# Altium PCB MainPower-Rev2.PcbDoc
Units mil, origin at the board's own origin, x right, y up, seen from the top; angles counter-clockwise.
Board outline 7780 x 7780 mil, 4 copper layers (Top Layer, Internal Plane 1, Internal Plane 2, Bottom Layer); 128 components, 89 nets, 530 pads, 24 vias.
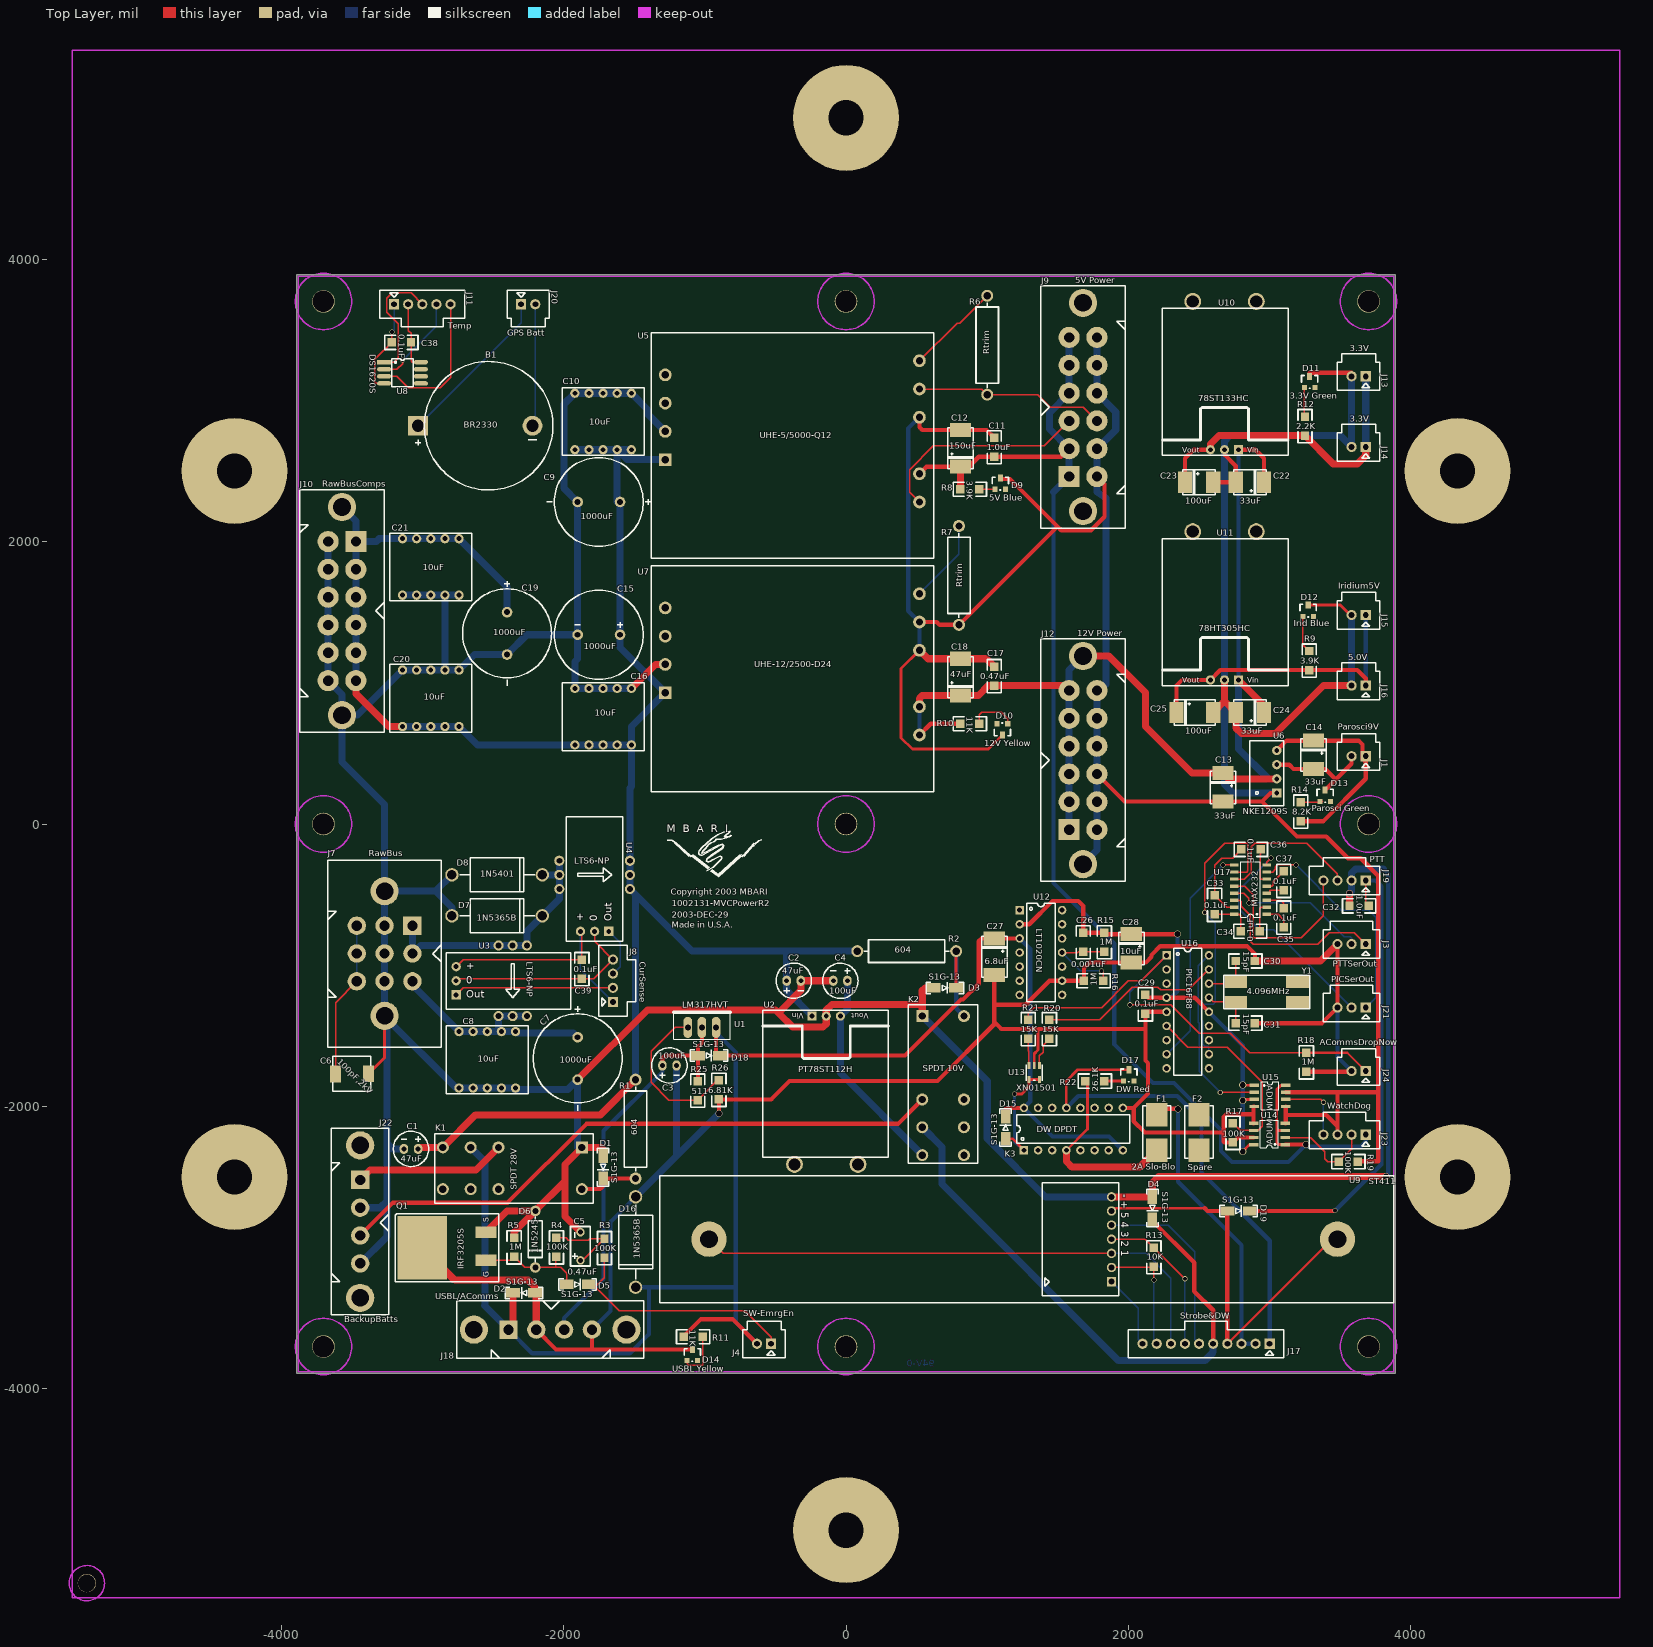
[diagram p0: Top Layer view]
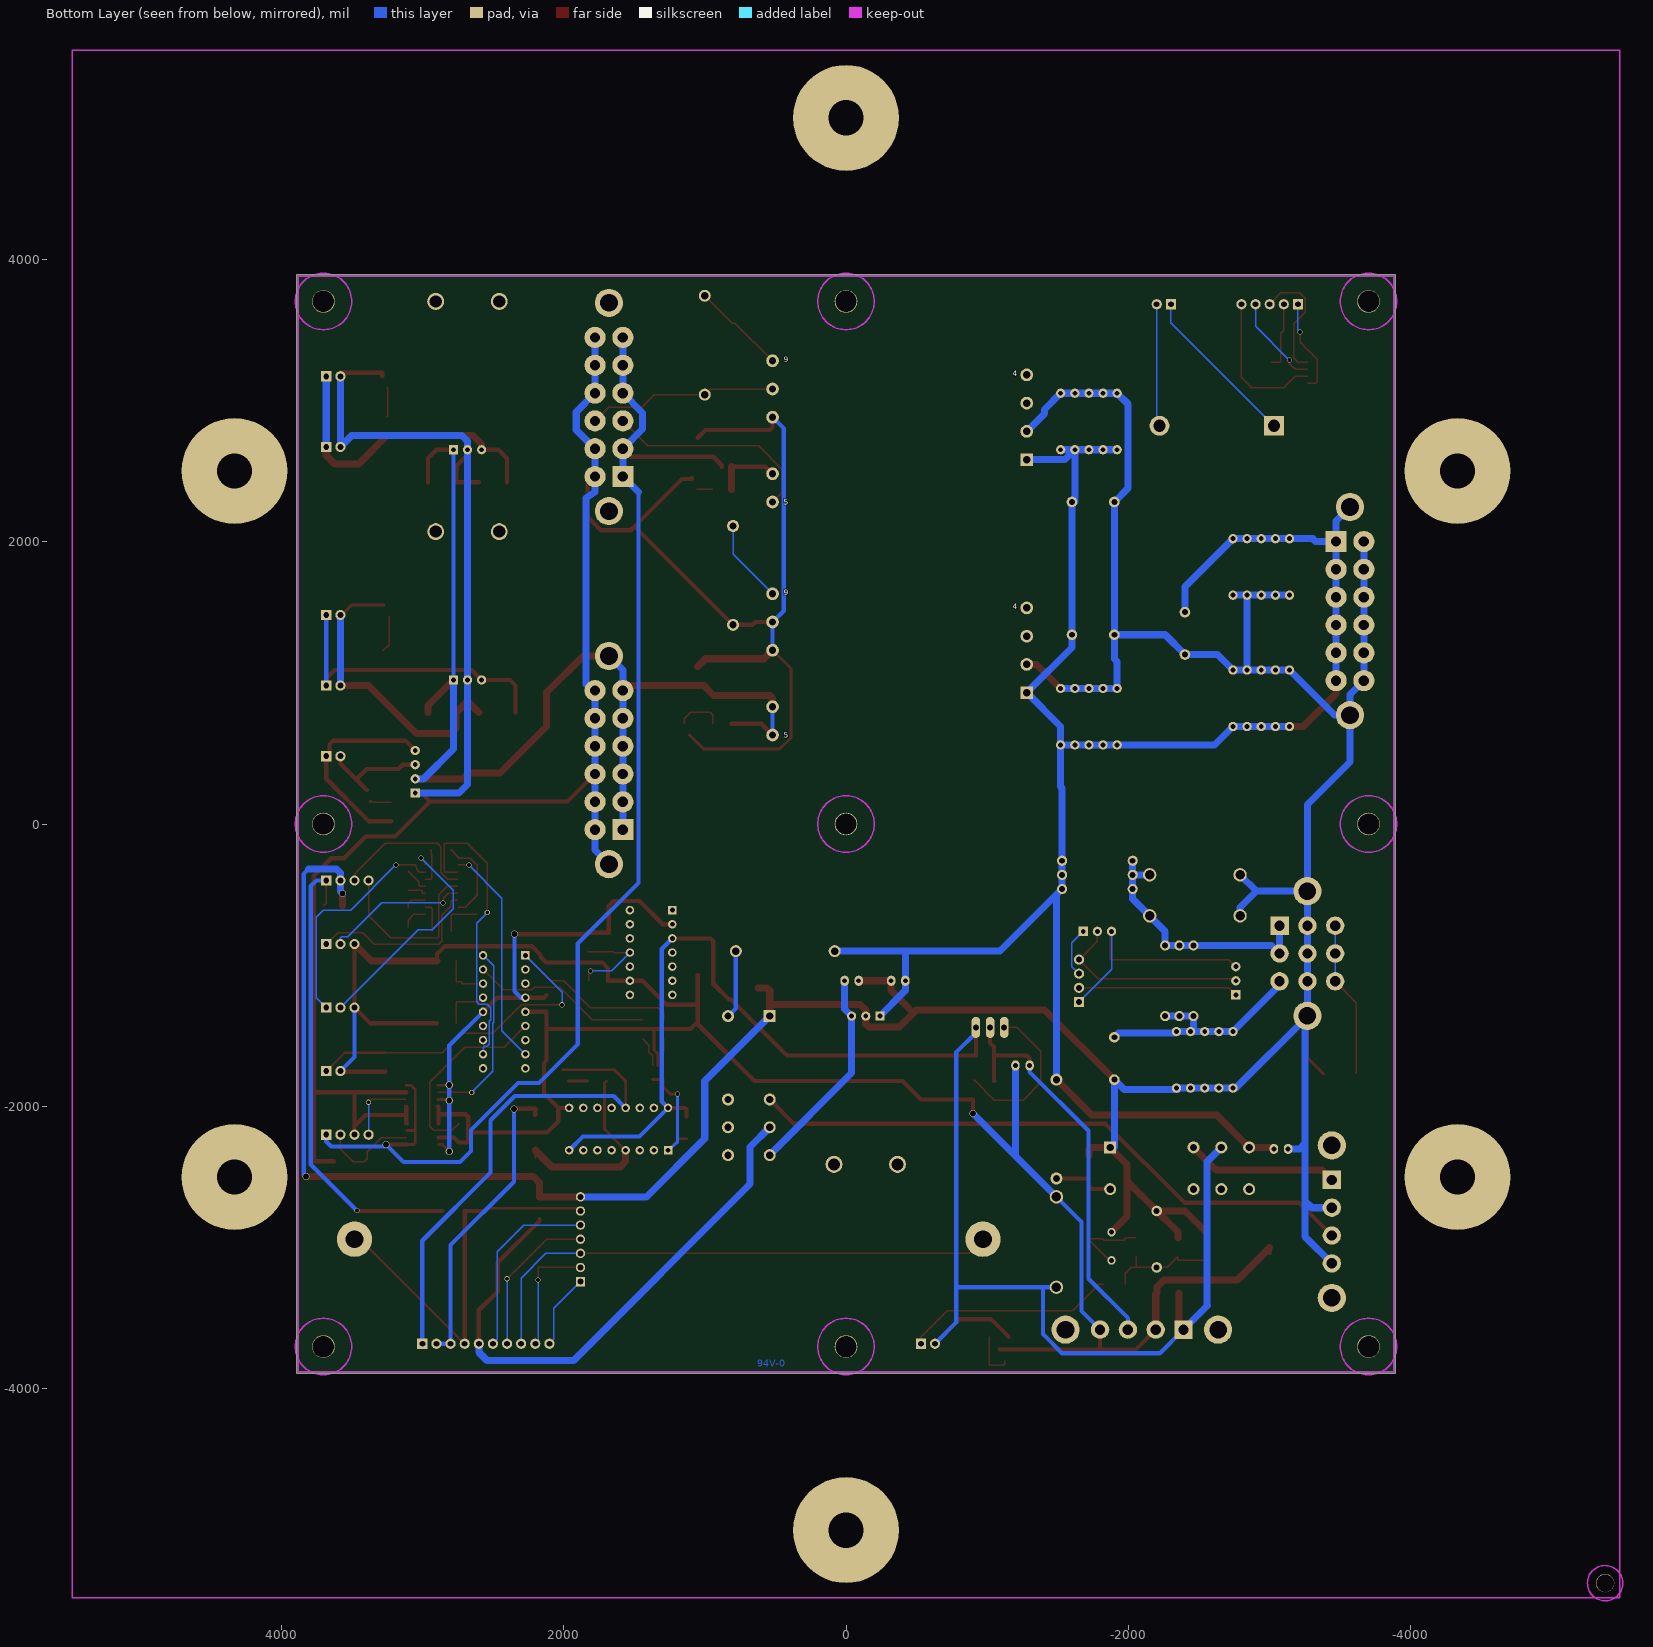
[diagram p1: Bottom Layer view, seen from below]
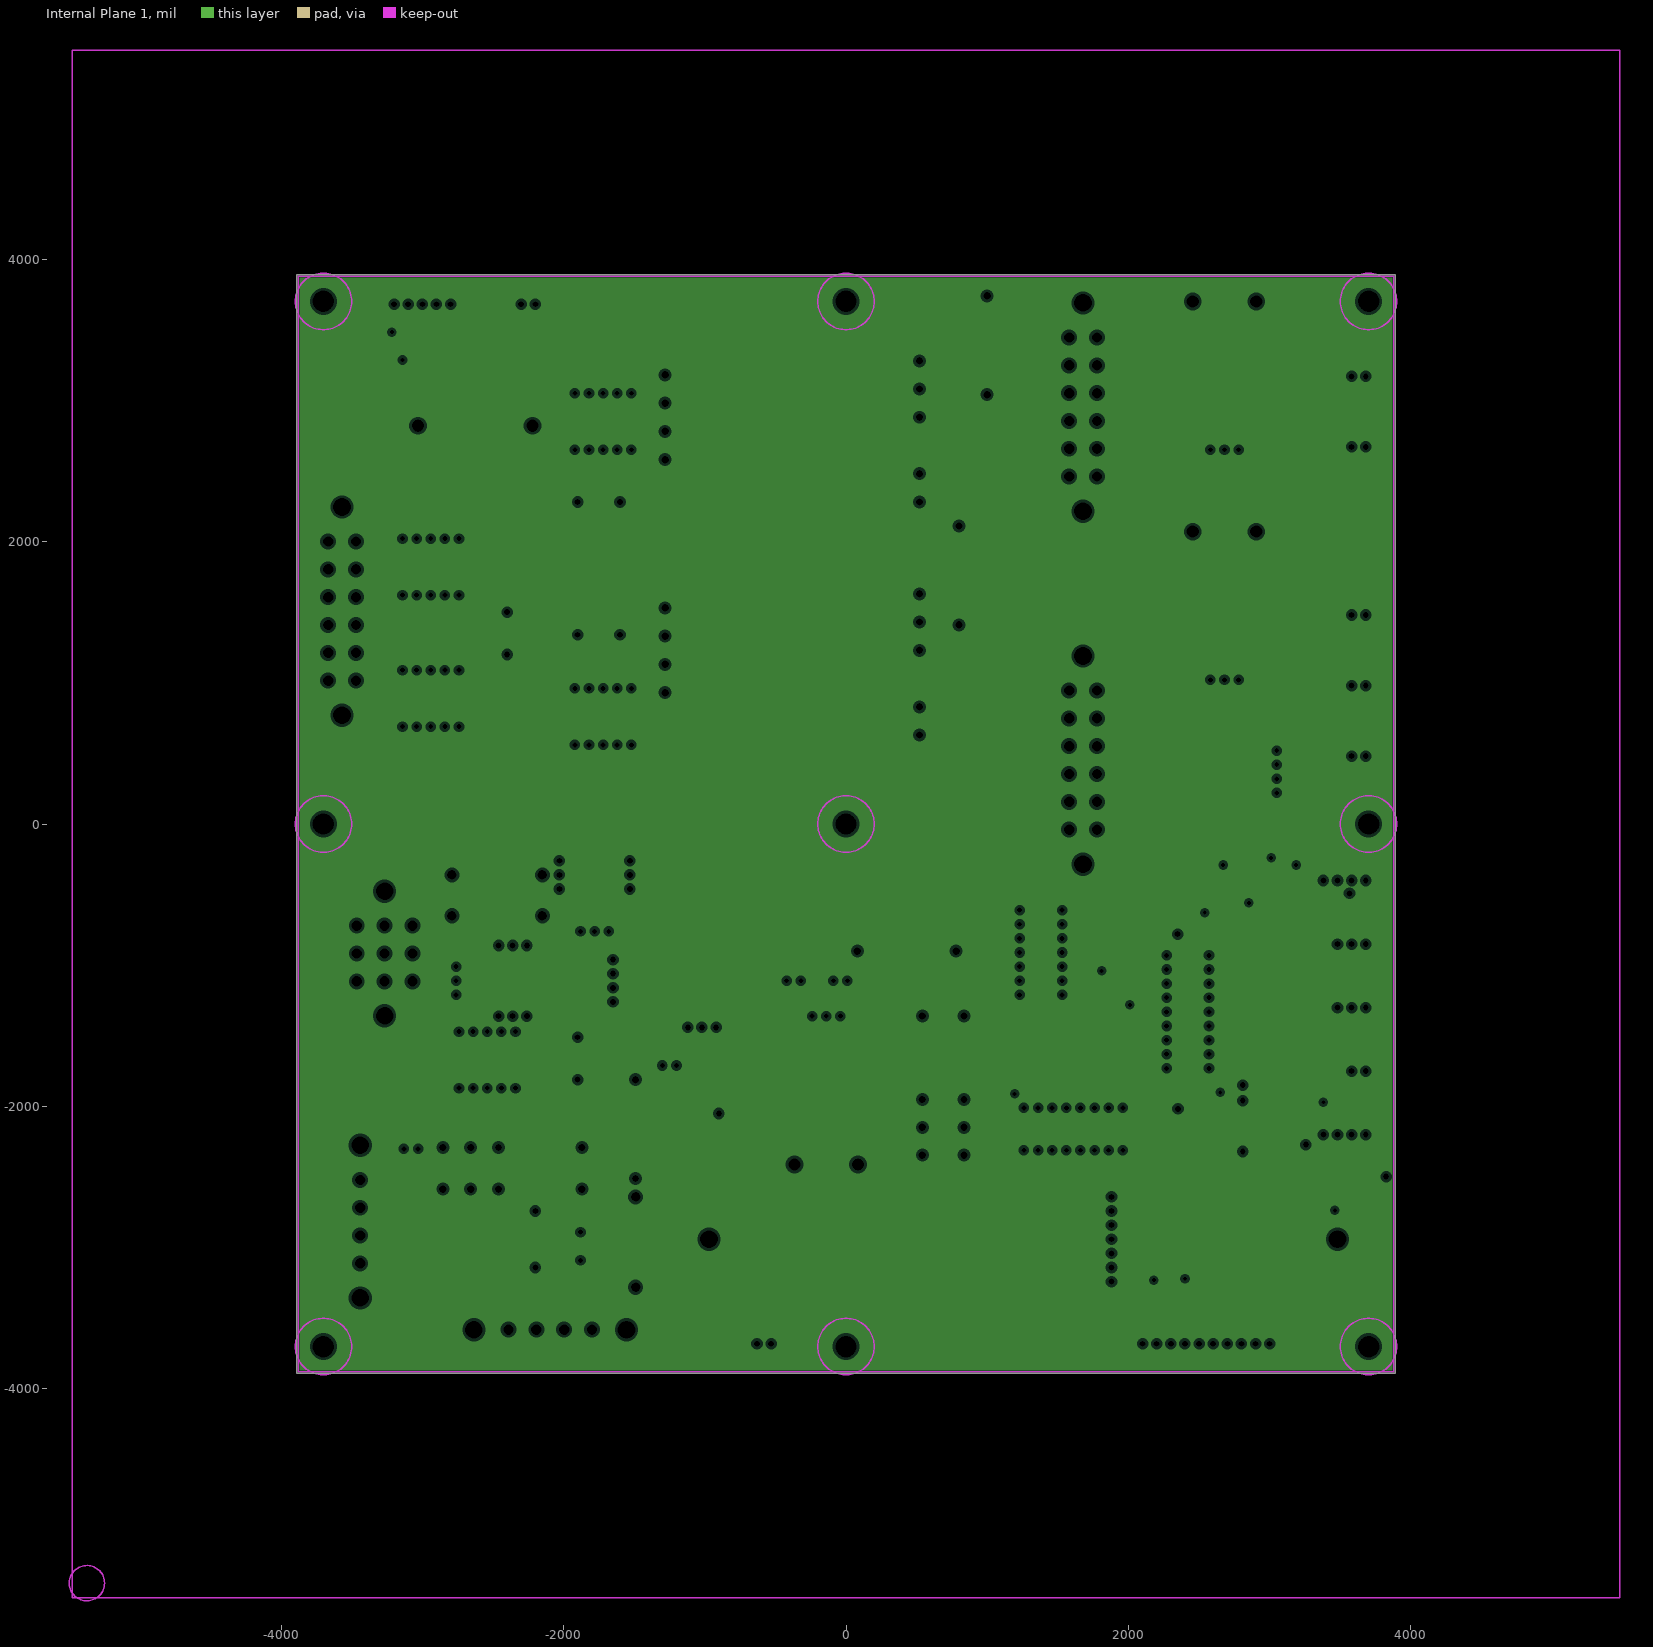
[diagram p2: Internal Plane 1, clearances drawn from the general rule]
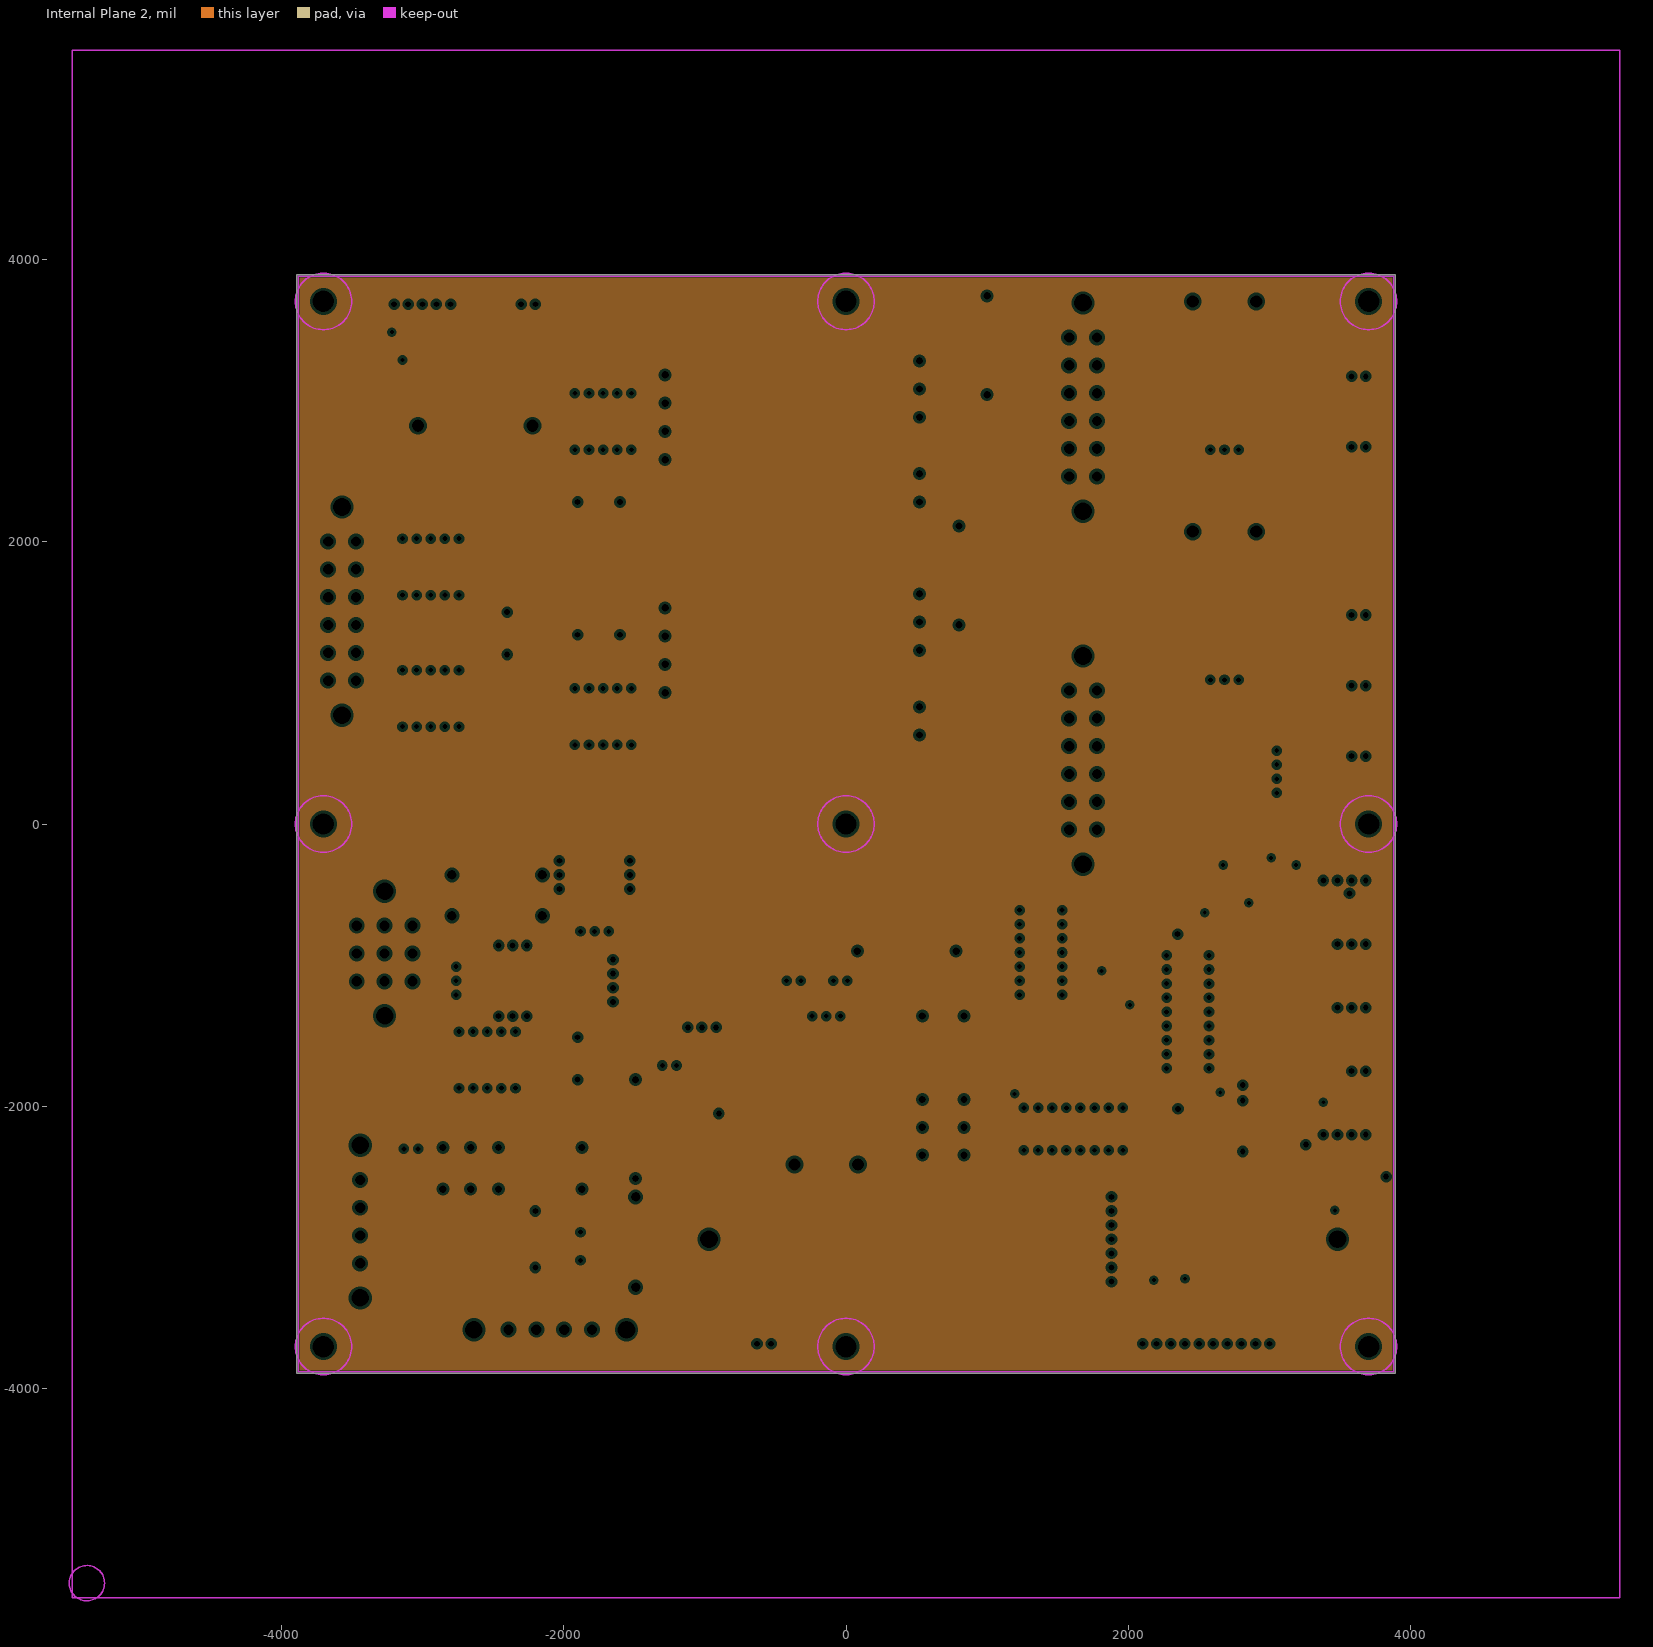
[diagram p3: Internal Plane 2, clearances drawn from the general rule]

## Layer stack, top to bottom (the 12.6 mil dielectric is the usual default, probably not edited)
Top Layer: signal copper 1.4
Dielectric: dielectric 12.6, FR-4, Dk 4.8
Internal Plane 1: plane copper 1.4
Dielectric: dielectric 12.6, FR-4, Dk 4.8
Internal Plane 2: plane copper 1.4
Dielectric: dielectric 12.6, FR-4, Dk 4.8
Bottom Layer: signal copper 1.4

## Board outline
-3890,3890 3890,3890 3890,-3890 -3890,-3890

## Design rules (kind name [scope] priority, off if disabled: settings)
Clearance Clearance_u13 [InPadClass('fineSMT')] p1: gap=10
Clearance powers [(InNetClass('BackupBattPower') OR InNetClass('RawPower') OR InNetClass('RegVoltage'))] p2: gap=20
Clearance [All] p3: gap=10
ComponentClearance [All] p1 off: gap=10 collisioncheckmode=0
FanoutControl Fanout_Small [(CompPinCount < 5)] p1: bgadir=Out bgaviamode=Centered fanoutstyle=Auto fanoutdirection=OutThenIn viagrid=1 // Fanout_Small (Default Rule)
FanoutControl Fanout_Default [All] p2: bgadir=Out bgaviamode=Centered fanoutstyle=Auto fanoutdirection=Alternating viagrid=1 // Fanout_Default (Default Rule)
FanoutControl Fanout_BGA [IsBGA] p4: bgadir=Out bgaviamode=Centered fanoutstyle=Auto fanoutdirection=Alternating viagrid=1 // Fanout_BGA (Default Rule)
FanoutControl Fanout_LCC [IsLCC] p5: bgadir=Out bgaviamode=Centered fanoutstyle=Auto fanoutdirection=Alternating viagrid=1 // Fanout_LCC (Default Rule)
HoleSize [All] p1: absolutevalues=TRUE maxlimit=250 minlimit=1 maxpercent=80.000 minpercent=20.000
PlaneClearance [All] p1: clearance=20
PlaneConnect [All] p1: planeconnectstyle=Relief reliefexpansion=20 reliefentries=4 reliefconductorwidth=10 reliefairgap=10
PolygonConnect [All] p1: connectstyle=Relief reliefconductorwidth=10 reliefentries=4 polygonreliefangle="90 Angle"
RoutingCorners [All] p1: cornerstyle=Round minsetback=50 maxsetback=1000
RoutingLayers [All] p1: top layer=Horizontal bottom layer=Vertical
RoutingPriority raw_powers [InNetClass('RawPower')] p1: routingpriority=90
RoutingPriority regpow [InNetClass('RegVoltage')] p2: routingpriority=70
RoutingPriority battpow [InNetClass('BackupBattPower')] p3: routingpriority=80
RoutingPriority [All] p4: routingpriority=0
RoutingVias RoutingVias_power [(InNetClass('BackupBattPower') OR InNetClass('RawPower') OR InNetClass('RegVoltage'))] p1: holewidth=42 width=50 viastyle="Through Hole" minholewidth=35 minwidth=43 maxholewidth=86 maxwidth=100
RoutingVias [All] p2: holewidth=28 width=36 viastyle="Through Hole" minholewidth=28 minwidth=35 maxholewidth=86 maxwidth=100
SolderMaskExpansion [All] p1: expansion=4
TestPointUsage [All] p1: valid=0 allowmultiple=FALSE
Testpoint [All] p1: side=15 testpointundercomponent=TRUE minsize=40 maxsize=100 preferedsize=60 minholesize=0 maxholesize=40 preferedholesize=32 testpointgrid=1 style=1023 order=1234567890
Width raw_power [InNetClass('RawPower')] p1: maxlimit=500 minlimit=10 preferedwidth=10 toplayer_minwidth=20 toplayer_prefwidth=50 bottomlayer_minwidth=20 bottomlayer_prefwidth=30 minimp=50.000000 maximp=50.000000 favimp=50.000000
Width backup_batt_pow [InNetClass('BackupBattPower')] p2: maxlimit=500 minlimit=10 preferedwidth=10 toplayer_minwidth=20 toplayer_prefwidth=30 bottomlayer_minwidth=20 bottomlayer_prefwidth=50 minimp=50.000000 maximp=50.000000 favimp=50.000000
Width reg_pow [InNetClass('RegVoltage')] p3: maxlimit=250 minlimit=10 preferedwidth=10 toplayer_minwidth=20 toplayer_prefwidth=20 bottomlayer_minwidth=20 bottomlayer_prefwidth=50 minimp=50.000000 maximp=50.000000 favimp=50.000000
Width [All] p4: maxlimit=500 minlimit=8 preferedwidth=12 toplayer_prefwidth=10 bottomlayer_prefwidth=10 minimp=50.000000 maximp=50.000000 favimp=50.000000
7 further rules are at their usual default settings.

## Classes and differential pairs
pad class fineSMT: U13-1 U13-2 U13-3 U13-4 U13-5 U14-1 U14-2 U14-3 U14-4 U14-5 U14-6 U14-7 U14-8 U15-1 U15-2 U15-3 U15-4 U15-5 U15-6 U15-7 U15-8 U16-4 U16-5
net class RawPower: ELEC+ LOCO+ RAWBUS+ RAWBUS-
net class RegVoltage: DW5V IRID5V+ MVC3.3V+ MVC5V+ MVC12V+ MVCGND PARO9V+ PARO9VGND SW10VDC V+USBL
net class BackupBattPower: 12VSWBU BACKUP10+ BACKUP28+ DW28V DW+ DW- DWGND SW10VDC V+USBL
component class BattBacked-Rev2: C1 C2 C3 C4 C5 D1 D2 D3 D4 D5 D6 D16 D18 J4 K1 K2 Q1 R1 R2 R3 R4 R5 R25 R26 U1 U2
component class GPS: C22 C23 U10
component class ISO5V-25W-MVC-Rev2: C9 C10 C11 C12 R6 U5
component class ISO12V-30W-MVC-Rev2: C15 C16 C17 C18 R7 U7
component class Input-Caps-Diodes-CurrentSensing: C6 C7 C8 C39 D7 D8 U3 U4
component class Iridium: C24 C25 U11
component class MainPower-Rev2: B1 C19 C20 C21 C32 C38 D9 D10 D11 D12 D13 D14 D19 J1 J7 J8 J9 J10 J11 J12 J13 J14 J15 J16 J17 J18 J19 J20 J22 J23 J24 R8 R9 R10 R11 R12 R13 R14 U8 U9
component class "Parosci Iso": C13 C14 U6
component class Watchdog-Rev2: C26 C27 C28 C29 C30 C31 C33 C34 C35 C36 C37 D15 D17 F1 F2 J3 J21 J25 J26 K3 R15 R16 R17 R18 R19 R20 R21 R22 R23 R24 U12 U13 U14 U15 U16 U17 Y1

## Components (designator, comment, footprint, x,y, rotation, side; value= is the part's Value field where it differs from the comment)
B1 "BR2330" BR2330-BAT -2530,2820 r180 top
C1 "47uF" RAD0.1L_0.25D -3030,-2300 r180 top
C2 "47uF" RAD0.1L_0.25D -420,-1110 r0 top
C3 "100uF" RAD0.1L_0.25D -1300,-1710 r0 top
C4 "100uF" RAD0.1L_0.25D 10,-1110 r180 top
C5 "0.47uF" RAD0.2_POL -1880,-3090 r90 top
C6 "100pF,2kV" ECK -3620,-1750 r0 top
C7 "1000uF" RAD0.3L_0.63D -1900,-1510 r270 top
C8 "10uF" CAPSTICK-CS4-5 -2740,-1470 r0 top
C9 "1000uF" RAD0.3L_0.63D -1600,2280 r180 top
C10 "10uF" CAPSTICK-CS4-5 -1520,2650 r180 top
C11 "1.0uF" 1206 1050,2600 r90 top
C12 "150uF" 7343pol 810,2530 r90 top
C13 "33uF" 6032pol 2670,360 r270 top
C14 "33uF" 6032pol 3310,590 r270 top
C15 "1000uF" RAD0.3L_0.63D -1600,1340 r180 top
C16 "10uF" CAPSTICK-CS4-5 -1520,560 r180 top
C17 "0.47uF" 1206 1050,980 r90 top
C18 "47uF" 7343pol 810,910 r90 top
C19 "1000uF" RAD0.3L_0.63D -2400,1500 r270 top
C20 "10uF" CAPSTICK-CS4-5 -2740,690 r180 top
C21 "10uF" CAPSTICK-CS4-5 -3140,2020 r0 top
C22 "33uF" 6032pol 2960,2420 r180 top
C23 "100uF" 6032pol 2400,2420 r0 top
C24 "33uF" 6032pol 2960,790 r180 top
C25 "100uF" 7343pol 2340,790 r0 top
C26 "0.001uF" 1206 1680,-770 r270 top
C27 "6.8uF" 7343pol 1050,-810 r270 top
C28 "10uF" 6032pol 2020,-780 r270 top
C29 "0.1uF" 1206 2120,-1210 r270 top
C30 "15pF" 1206 2760,-970 r0 top
C31 "15pF" 1206 2760,-1410 r0 top
C32 "1.0uF" 1206 3700,-580 r180 top
C33 "0.1uF" 1206 2610,-640 r90 top
C34 "0.1uF" 1206 2930,-760 r180 top
C35 "0.1uF" 1206 3100,-730 r90 top
C36 "0.1uF" 1206 2800,-180 r0 top
C37 "0.1uF" 1206 3100,-470 r90 top
C38 "0.1uF" 1206 -3080,3410 r180 top
C39 "0.1uF" 1206 -1870,-960 r270 top
D1 "S1G-13" SMA -1720,-2430 r270 top
D2 "S1G-13" SMA -2280,-3320 r180 top
D3 "S1G-13" SMA 700,-1160 r0 top
D4 "S1G-13" SMA 2170,-2720 r270 top
D5 "S1G-13" SMA -1900,-3260 r0 top
D6 "1N5245" DIODE0.4 -2200,-2740 r270 top
D7 "1N5365B" DO-201AD -2790,-650 r0 top
D8 "1N5401" DO-201AD -2790,-360 r0 top
D9 "5V Blue" SOT-23 1130,2370 r0 top
D10 "12V Yellow" SOT-23 1070,710 r180 top
D11 "3.3V Green" SOT-23 3320,3090 r0 top
D12 "Irid Blue" SOT-23 3310,1470 r0 top
D13 "Parosci Green" SOT-23 3430,160 r0 top
D14 "USBL Yellow" SOT-23 -1050,-3800 r0 top
D15 "S1G-13" SMA 1130,-2150 r90 top
D16 "1N5365B" DO-201AD -1490,-2640 r270 top
D17 "DW Red" SOT-23 2040,-1820 r0 top
D18 "S1G-13" SMA -970,-1640 r0 top
D19 "S1G-13" SMA 2780,-2740 r0 top
F1 "2A Slo-Blo" SMF-OMNIBLOK 2200,-2310 r90 top
F2 "Spare 2A Slo-Blo" SMF-OMNIBLOK 2500,-2310 r90 top
J1 "Parosci9V" CGRID2 3680,480 r0 top
J3 "PTTSerOut" CGRID3 3680,-850 r0 top
J4 "SW-EmrgEn" CGRID2 -530,-3680 r0 top
J7 "RawBus" PLC09 -3070,-720 r270 top
J8 "CurSense" CGRID4 -1650,-1260 r270 top
J9 "5V Power" PLB12 1580,2460 r90 top
J10 "RawBusComps" PLB12 -3470,2000 r270 top
J11 "Temp" CGRID5 -3200,3680 r180 top
J12 "12V Power" PLB12 1580,-40 r90 top
J13 "3.3V" CGRID2 3680,3170 r0 top
J14 "3.3V" CGRID2 3680,2670 r0 top
J15 "Iridium5V" CGRID2 3680,1480 r0 top
J16 "5.0V" CGRID2 3680,980 r0 top
J17 "Strobe&DW" CGRID10 3000,-3680 r0 top
J18 "USBL/AComms" PLA04 -2390,-3580 r0 top
J19 "PTT" CGRID4 3680,-400 r0 top
J20 "GPS Batt" CGRID2 -2300,3680 r180 top
J21 "PICSerOut" CGRID3 3680,-1300 r0 top
J22 "BackupBatts" PLA04 -3440,-2520 r270 top
J23 "WatchDog" CGRID4 3680,-2200 r0 top
J24 "ACommsDropNow" CGRID2 3680,-1750 r0 top
K1 "SPDT 28V" NAIS-LZ -1870,-2290 r180 top
K2 "SPDT 10V" NAIS-LZ 540,-1360 r270 top
K3 "DW DPDT" DIP16 1260,-2310 r90 top
Q1 "IRF3205S" D2PAK -2550,-3090 r90 top
R1 "604" AXIAL0.7 -1490,-2510 r90 top
R2 "604" AXIAL0.7 780,-900 r180 top
R3 "100K" 1206 -1710,-3070 r90 top
R4 "100K" 1206 -2050,-2930 r270 top
R5 "1M" 1206 -2350,-2930 r270 top
R6 "Rtrim" AXIAL0.7 1000,3740 r270 top
R7 "Rtrim" AXIAL0.7 800,2110 r270 top
R8 "3.9K" 1206 810,2370 r0 top
R9 "3.9K" 1206 3280,1090 r90 top
R10 "11K" 1206 810,710 r0 top
R11 "11K" 1206 -1150,-3630 r0 top
R12 "2.2K" 1206 3250,2750 r90 top
R13 "10K" 1206 2180,-3000 r270 top
R14 "8.2K" 1206 3220,20 r90 top
R15 "1M" 1206 1830,-770 r270 top
R16 "1M" 1206 1820,-1110 r180 top
R17 "100K" 1206 2740,-2120 r270 top
R18 "1M" 1206 3260,-1620 r270 top
R19 "100K" 1206 3490,-2390 r0 top
R20 "15K" 1206 1440,-1520 r90 top
R21 "15K" 1206 1290,-1520 r90 top
R22 "26.1K" 1206 1830,-1820 r180 top
R25 "511" 1206 -1050,-1820 r270 top
R26 "6.81K" 1206 -900,-1950 r90 top
U1 "LM317HVT" TO-220 -1120,-1440 r0 top
U2 "PT78ST112H" PT78ST-HORIZ -140,-1360 r180 top
U3 "LTS6-NP" LTS6-NP -2830,-910 r0 top
U4 "LTS6-NP" LTS6-NP -1980,-830 r90 top
U5 "UHE-5/5000-Q12" DATEL-UHE -1280,2580 r0 top locked
U6 "NKE1209S" NKEDCDC 3050,220 r180 top
U7 "UHE-12/2500-D24" DATEL-UHE -1280,930 r0 top locked
U8 "DS1620S" SOIC-8 -3270,3270 r0 top
U9 "ST411" ST411 3880,-2940 r270 top locked
U10 "78ST133HC" PT78ST-HORIZ 2680,2650 r0 top
U11 "78HT305HC" PT78ST-HORIZ 2680,1020 r0 top
U12 "LT1020CN" DIP14 1230,-610 r0 top
U13 "XN01501" SC-74A 1370,-1810 r0 top
U14 "ADUM1100AR" SO-G8/D5 3110,-2270 r90 top
U15 "ADUM1100AR" SO-G8/D5 2890,-1850 r270 top
U16 "PIC16F88" DIP18 2270,-930 r0 top
U17 "MAX232" SOIC-16-0.15W 2980,-640 r90 top
Y1 "4.096MHz" MA-506 2760,-1260 r0 top

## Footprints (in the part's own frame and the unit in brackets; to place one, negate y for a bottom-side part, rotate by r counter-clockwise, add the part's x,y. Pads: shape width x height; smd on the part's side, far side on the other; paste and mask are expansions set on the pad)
1206 [mil]
  rect 60x60 smd: 1(0,0) 2(135,0)
  silkscreen extent -50,-50 185,50
6032pol [mil]
  rect 100x150 smd: 1(0,0) 2(200,0)
  silkscreen extent -15,-90 215,90
7343pol [mil]
  rect 100x150 smd: 1(0,0) 2(260,0)
  silkscreen extent -15,-90 275,90
AXIAL0.7 [mil]
  round 85 hole 52: 1(0,0) 2(700,0)
  silkscreen extent 50,-80 650,80
BR2330-BAT [mil] "BR2330 lithium battery horiz mounted"
  rect 140x140 hole 86: 1(500,0)
  round 140 hole 86: 2(-310,0)
  silkscreen extent -455,-455 520,455
CAPSTICK-CS4-5 [mil]
  round 66 hole 35: 1(0,0) 1(100,0) 1(200,0) 1(300,0) 1(400,0) 2(0,-400) 2(100,-400) 2(200,-400) 2(300,-400) 2(400,-400)
  silkscreen extent -90,-440 490,40
CGRID2 [mil]
  rect 72x72 hole 42: 1(0,0)
  round 72 hole 42: 2(-100,0)
  silkscreen extent -200,-100 100,160
CGRID3 [mil]
  rect 72x72 hole 42: 1(0,0)
  round 72 hole 42: 2(-100,0) 3(-200,0)
  silkscreen extent -300,-100 100,160
CGRID4 [mil]
  rect 72x72 hole 42: 1(0,0)
  round 72 hole 42: 2(-100,0) 3(-200,0) 4(-300,0)
  silkscreen extent -400,-100 100,160
CGRID5 [mil]
  rect 72x72 hole 42: 1(0,0)
  round 72 hole 42: 2(-100,0) 3(-200,0) 4(-300,0) 5(-400,0)
  silkscreen extent -500,-100 100,160
CGRID10 [mil] "10 pin Molex CGRID-SL straight"
  rect 72x72 hole 42: 1(0,0)
  round 72 hole 42: 2(-100,0) 3(-200,0) 4(-300,0) 5(-400,0) 6(-500,0) 7(-600,0) 8(-700,0) 9(-800,0) 10(-900,0)
  silkscreen extent -1000,-100 100,160
D2PAK [mil] "IRF D2Pak SMD-220"
  rect 82x150 smd: 1(0,0) 3(200,0)
  rect 450x350 smd: 2(90,450)
  silkscreen extent -150,-90 330,640
DATEL-UHE [mil] "Datel UHE 1.6x2.0 DC/DC Converter"
  rect 90x90 hole 52: 1(0,0)
  round 90 hole 52: 2(0,200) 3(0,400) 4(0,600) 5(1800,-300) 6(1800,-100) 7(1800,300) 8(1800,500) 9(1800,700)
  silkscreen extent -100,-700 1900,900
DIODE0.4 [mil]
  round 75 hole 42: 1(0,0) 2(400,0)
  silkscreen extent 40,-50 360,50
DIP14 [mil]
  rect 60x60 hole 35: 1(0,0)
  round 60 hole 35: 2(0,-100) 3(0,-200) 4(0,-300) 5(0,-400) 6(0,-500) 7(0,-600) 8(300,-600) 9(300,-500) 10(300,-400) 11(300,-300) 12(300,-200) 13(300,-100) 14(300,0)
  silkscreen extent 50,-650 250,50
DIP16 [mil]
  rect 60x60 hole 35: 1(0,0)
  round 60 hole 35: 2(0,-100) 3(0,-200) 4(0,-300) 5(0,-400) 6(0,-500) 7(0,-600) 8(0,-700) 9(300,-700) 10(300,-600) 11(300,-500) 12(300,-400) 13(300,-300) 14(300,-200) 15(300,-100) 16(300,0)
  silkscreen extent 50,-750 250,50
DIP18 [mil]
  rect 60x60 hole 35: 1(0,0)
  round 60 hole 35: 2(0,-100) 3(0,-200) 4(0,-300) 5(0,-400) 6(0,-500) 7(0,-600) 8(0,-700) 9(0,-800) 10(300,-800) 11(300,-700) 12(300,-600) 13(300,-500) 14(300,-400) 15(300,-300) 16(300,-200) 17(300,-100) 18(300,0)
  silkscreen extent 50,-850 250,50
DO-201AD [mil]
  round 95 hole 67: 1(0,0) 2(640,0)
  silkscreen extent 55,-120 585,120
ECK [mm]
  rect 2x3 smd: 1(0.15,-0.5) 2(6.075,-0.475)
  silkscreen extent -0.4,-3.6 6.5,2.7
LTS6-NP [mil]
  round 72 hole 42: 1(370,-450) 2(470,-450) 3(570,-450) 4(570,50) 5(470,50) 6(370,50)
  rect 66x66 hole 35: a(70,-300)
  round 66 hole 35: b(70,-200) c(70,-100)
  silkscreen extent 0,-400 880,0
MA-506 [mm] "Epson Quartz Crystal"
  rect 4.1x2.1 smd: 1(0,0) 2(11.1,0) 3(11.1,3.6) 4(0,3.6)
  silkscreen extent -2.2,-1.2 13.3,4.8
NAIS-LZ [mil] "NAIS LZ Relay"
  rect 85x85 hole 52: 1(0,0)
  round 85 hole 52: 2(590.55,0) 3(787.4,0) 4(984.25,0) 5(984.25,295.28) 6(787.4,295.28) 7(590.55,295.28) 8(0,295.28)
  silkscreen extent -79,-98 1043,394
NKEDCDC [mil]
  rect 66x66 hole 35: 1(0,0)
  round 66 hole 35: 2(0,-100) 3(0,-200) 4(0,-300)
  silkscreen extent -50,-370 190,90
PLA04 [mil] "Positronic 1x4 pin"
  round 200 hole 125: 0(-244.5,0) 0(835.5,0)
  rect 130x130 hole 73: 1(0,0)
  round 130 hole 73: 2(197,0) 3(394,0) 4(591,0)
  silkscreen extent -366,-204 956,204
PLB12 [mil] "Positronic 2x6 pin"
  round 200 hole 125: 0(-244.5,-98.5) 0(1229.5,-98.5)
  rect 150x150 hole 73: 1(0,0)
  round 150 hole 73: 2(197,0) 3(394,0) 4(591,0) 5(788,0) 6(985,0) 7(0,-197) 8(197,-197) 9(394,-197) 10(591,-197) 11(788,-197) 12(985,-197)
  silkscreen extent -366,-398 1350,202
PLC09 [mil] "Positronic 3x3 pins"
  round 200 hole 125: 0(-244.5,-197) 0(638.5,-197)
  rect 130x130 hole 73: 1(0,0)
  round 130 hole 73: 2(197,0) 3(394,0) 4(0,-197) 5(197,-197) 6(394,-197) 7(0,-394) 8(197,-394) 9(394,-394)
  silkscreen extent -465,-598 859,205
PT78ST-HORIZ [mil]
  round 120 hole 86: 0(-225,1050) 0(225,1050)
  rect 65x65 hole 35: 1(100,0)
  round 65 hole 35: 2(0,0) 3(-100,0)
  silkscreen extent -440,-40 450,1000
RAD0.1L_0.25D [mil]
  oval 60x72 hole 35: 1(0,0) 2(100,0)
  silkscreen extent -75,-125 175,125
RAD0.2_POL [mil] "Polarized Cap"
  round 60 hole 35: 1(0,0) 2(200,0)
  silkscreen extent -40,-70 240,70
RAD0.3L_0.63D [mil]
  round 75 hole 42: 1(0,0) 2(300,0)
  silkscreen extent -220,-315 520,315
SC-74A [mil] "Mini5 - G1 Panasonic"
  rect 20x50 smd: 1(0,0) 2(-75,0) 3(-75,100) 4(-37,100) 5(0,100)
  silkscreen extent -95,-8 19,106
SMA [mm] "SMA Diode"
  rect 2.5x1.7 smd: 1(-2,0) 2(2,0)
  silkscreen extent -3.38,-1.02 3.38,1.02
SMF-OMNIBLOK [mil] "SMD Nano Fuse Holder"
  rect 167x150 smd: 1(0,0) 2(250,0)
  silkscreen extent -55,-100 315,100
SO-G8/D5 [mm]
  rect 0.6x1.7 smd: 1(0,0) 2(1.27,0) 3(2.54,0) 4(3.81,0) 5(3.81,5.7) 6(2.54,5.7) 7(1.27,5.7) 8(0,5.7)
  silkscreen extent -0.59,1.25 4.41,4.45
SOIC-8 [mil]
  rect 100x30 smd: 1(0,0)
  oval 100x30 smd: 2(0,-50) 3(0,-100) 4(0,-150) 5(260,-150) 6(260,-100) 7(260,-50) 8(260,0)
  silkscreen extent 55,-175 205,25
SOIC-16-0.15W [mm] "SOIC-16 0.15\"Wide 1.27mm Pitch"
  rect 0.6x1.55 smd: 1(0,0) 2(1.27,0) 3(2.54,0) 4(3.81,0) 5(5.08,0) 6(6.35,0) 7(7.62,0) 8(8.89,0) 9(8.89,5.85) 10(7.62,5.85) 11(6.35,5.85) 12(5.08,5.85) 13(3.81,5.85) 14(2.54,5.85) 15(1.27,5.85) 16(0,5.85)
  silkscreen extent -0.55,1.18 9.44,4.67
SOT-23 [mil]
  rect 36x36 smd: 1(0,0) 2(-75,0)
  rect 36x50 smd: 3(-37,80)
  silkscreen extent -95,-5 20,85
ST411 [mil]
  round 250 hole 125: 00(0,-400) 0(0,-4850)
  rect 66x66 hole 42: 1(300,-2000)
  round 66 hole 42: 2(200,-2000) 3(100,-2000) 4(0,-2000) 5(-100,-2000) 6(-200,-2000) 7(-300,-2000)
  silkscreen extent -450,-5200 450,0
TO-220 [mil]
  oval 60x150 hole 42: 1(0,0) 2(100,0) 3(200,0)
  silkscreen extent -100,-85 300,108

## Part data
B1: library part Battery, "Multicell Battery"
C1 C2 C3 C4 C5 C7 C9 C13 C14 C15 C19 C22 C23 C24 C25 C27 C28: library part "CAPACITOR POL", "Capacitor"
C6 C8 C10 C11 C16 C17 C20 C21 C26 C29 C30 C31 C32 C33 C34 C35 C36 C37 C38 C39: library part CAPACITOR, "Capacitor"
C12 C18: library part "CAPACITOR POL", "Tantalum Capacitor"
D1 D2 D3 D4 D5 D8 D15 D18 D19: library part DIODE_S, "Diode"
D6 D7 D16: library part ZENER3, "Zener Diode"
D9 D10 D11 D12 D13 D14 D17: library part LED, "LED"
F1 F2: library part "Fuse 2", "Fuse"
J1 J4 J19 J20: library part CON2, "Connector"
J3 J21: library part CON3, "Connector"
J7: library part CON3X3-PLC, "Positronic 9 pin connector"
J8: library part CON4, "Connector"
J9 J10 J12: library part CON12-PLB-2, "Positronic 12 pin connector"
J11: library part CON5, "Connector"
J13 J14 J15 J16 J24: library part CON2, "Connector C-Grid"
J17: library part CON10, "Connector"
J18 J22: library part CON4-PLA, "Positronic 4 pin connector"
J23: library part CON4, "Connector C-Grid"
K1 K2: library part RELAY-NAIS-LZ-SPDT, "Nais LZ Relay SPDT"
K3: library part RELAY-PB-V23105, "P&B V23105 Relay DPDT"
Q1: library part HEXFET-N, "HexFET"
R1 R2 R3 R4 R5 R6 R7 R8 R9 R10 R11 R12 R13 R14 R15 R16 R17 R18 R19 R20 R21 R22 R25 R26: library part RESISTOR, "Resistor"
U1: "Regulator"
U2 U10: library part PT78STXXX, "Power Trends Switching Reg"
U3 U4: "Current Transducer"
U5 U7: library part UHE, "Datel UHE DC->DC Isolated Converter"
U6: "DC->DC Isol Converter 12->9VDC"
U8: library part DS1620, "DallasSemi Digital Thermometer and Thermostat"
U9: "Novatech Strobe Beacon"
U11: library part PT78STXXX, "Power Trends Switching Reg 5V, 3A"
U12: library part LT1020, "Micropower Regulator"
U13: "Dual NPN Common Emitter Transistor"
U14 U15: "Digital Isolator"
U16: "PIC16F88 microcontroller DIP,SOIC package"
U17: "MAX232 Communications Chip"
Y1: library part XTAL, "Crystal Oscillator"

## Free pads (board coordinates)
  round 130 hole 125: 0(-5375,-5375)
  round 160 hole 152: 0(-3700,-3700) 1(-3700,0) 1(0,-3700) 1(0,0) 1(0,3700) 1(3700,-3700) 1(3700,0) 2(3700,3700) 3(-3700,3700)
  round 750 hole 250: 0(0,5000) 1(0,-5000) 2(-4330,-2500) 2(-4330,2500) 3(4330,-2500) 3(4330,2500)

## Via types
v1: diameter 36, hole 28, Top Layer to Bottom Layer, 15 vias
v2: diameter 50, hole 42, Top Layer to Bottom Layer, 9 vias

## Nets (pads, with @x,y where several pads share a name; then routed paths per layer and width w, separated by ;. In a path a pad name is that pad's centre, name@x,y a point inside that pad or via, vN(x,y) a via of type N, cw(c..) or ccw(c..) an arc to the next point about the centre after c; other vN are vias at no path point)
12VSWBU: C4.1 K2.4 U2.3 | length 1495.2
  Bottom Layer w50: C4.1 10,-1310 U2.3 -40,-1764.25 K2.4
AN0V: C39.2 J8.4 U3.b U4.b | length 1426
  Top Layer w10: U3.b -2745,-1095 C39.2 -1785,-1095 J8.4 -1780,-830 U4.b
AN5V: C39.1 J8.1 U3.c U4.c | length 1710.1
  Top Layer w10: U3.c -2710,-960 C39.1 -1870,-770 U4.c
  Bottom Layer w10: U4.c -1880,-1030 J8.1
BACKUP10+: J22.3 K2.2 | length 4379.1
  Top Layer w30: J22.3 -3207,-2681 -2396,-2681 -1838,-2123 367.55,-2123 K2.2
BACKUP28+: J22.1 K1.2 | length 1074.7
  Top Layer w50: J22.1 -3370,-2450 -2620.55,-2450 K1.2
DROPNOW: J24.1 R18.1 R21.2 U16.1 | length 3517.2
  Top Layer w10: R21.2 1290,-1340 1330,-1300 1810,-1300 2000,-1110 2090,-1110 U16.1 ; v1(2010,-1280) 2300,-1280 2500,-1480 2520,-1480 2720,-1480 2860,-1620 R18.1
  Top Layer w15: R18.1 3550,-1620 J24.1
  Bottom Layer w10: v1(2010,-1280) 2010,-1190 U16.1
DW5V: C26.1 C28.1 C29.1 R15.1 U12.2 U14.8 U15.1 U15.3 U16.4 U16.14 | length 3757.3
  Top Layer w20: v2(2809,-2319) 2858,-2270 U14.8 ; v2(2809,-1959) 2810,-1950 U15.3 ; v2(2809,-1849) 2810,-1850 U15.1
  Top Layer w30: U12.2 1297,-710 1462.36,-544.64 1644.64,-544.64 1680,-580 C26.1 R15.1 1830,-780 C28.1 v2(2348,-780) ; C29.1 2140,-1230 U16.4 2470,-1230 U16.14
  Bottom Layer w30: U16.4 2302,-1230 2348,-1184 v2(2348,-780) ; U16.14 2809,-1569 v2(2809,-1849) v2(2809,-1959) v2(2809,-2319)
DW28V: C27.1 D2.2 D15.2 D16.2 D18.2 J4.2 J18.1 K1.3 K3.8 K3.16 R11.1 U1.3 U12.3 | length 11972.1
  Top Layer w30: R11.1 -1026,-3506 -804,-3506 J4.2 ; U1.3 -920,-1640 D18.2 417,-1640 814,-1243 828,-1243 940,-1131 940,-830 960,-810 C27.1 U12.3 ; D15.2 1130,-2020 1140,-2010 K3.16
  Top Layer w50: J18.1 -2358.74,-3548.74 D2.2
  Bottom Layer w30: J18.1 -2222,-3748 -1531,-3748 -1395,-3612 -1395,-3280 ; D16.2 -1395,-3280 ; U1.3 -920,-1478 -780,-1618 -780,-3280 ; J4.2 -780,-3530 -780,-3280 ; U12.3 1305,-885 1305,-1965 K3.16 1463,-2213 1863,-2213 K3.8 ; -1395,-3280 -780,-3280
  Bottom Layer w50: K1.3 -2557.44,-2389.97 -2557.44,-3411.16 ; -2559.44,-3409.16 J18.1
DW+: F1.2 J17.2 J17.3 | length 2143
  Top Layer w30: F1.2 2200,-2017 v2(2351,-2017)
  Bottom Layer w30: v2(2351,-2017) 2351,-2533 2800,-2982 J17.3 J17.2
DW-: D17.3 J17.1 K3.13 | length 3511.2
  Top Layer w20: K3.13 1560,-1820 1640,-1740 D17.3
  Bottom Layer w30: K3.13 1644,-1926 2345,-1926 2517,-2098 2517,-2468 3000,-2951 J17.1
DWGND: C3.2 C27.2 C28.2 C29.2 C30.2 C31.2 D2.1 D14.3 D16.1 J3.3 J18.2 J18.4 J21.3 J24.2 K3.9 Q1.2 R16.2 R17.2 R18.2 R26.1 U12.9 U13.4 U14.5 U14.7 U15.4 U16.5 | length 16227.3
  Top Layer w20: U13.4 1333,-1627 1360,-1600 1360,-1452
  Top Layer w30: Q1.2@-3000,-3036 Q1.2 ; J18.2 -2053,-3720 -1799,-3720 ; J18.4 -1799,-3720 ; D14.3 -1799,-3720 ; v2(-900,-2050) R26.1 -530,-1950 -400,-1820 648,-1820 1050,-1418 1050,-1402 ; 1050,-1280 1270,-1280 1440,-1110 U12.9 R16.2 1685,-1020 1725,-980 C28.2 2123,-980 2163,-940 2163,-927 2225.15,-864.85 2839.85,-864.85 2895,-920 C30.2 ; C27.2 1050,-1402 ; K3.9 2036.75,-2010 ; U16.5 2120,-1330 C29.2 2120,-1452 ; U14.7 2775,-2220 R17.2 2680,-2255 2674.42,-2249.42 2674.42,-2185 ; U14.5 2885,-2120 2885,-2055 ; U15.4 2885,-2000 2885,-2055 ; C31.2 3370,-1410 J21.3 J3.3 ; R18.2 3575,-1755 J24.2 ; 1050,-1402 1100,-1452 2120,-1452 ; 2036.75,-2010 2036.75,-2105 2116.75,-2185 2674.42,-2185 ; 2036.75,-2010 2138.38,-1908.37 2138.38,-1693.38 2120,-1675 2120,-1452 ; 2674.42,-2185 2674.42,-2075.42 2694.84,-2055 2885,-2055
  Top Layer w50: Q1.2 -2770,-3230 -2250,-3230 -2201.26,-3278.74 D2.1 -2193,-3328.26 J18.2 ; C30.2 3360,-970 J3.3
  Bottom Layer w30: J18.4 -1667,-3448 -1667,-2817 D16.1 ; J21.3 3480,-1650 3530,-1700 J24.2
  Bottom Layer w50: D16.1 -1200,-2350 ; C3.2 -1200,-2350 ; v2(-900,-2050) -1200,-2350
ELEC+: C1.1 C2.1 C9.1 C10.1 C15.1 C16.1 C19.1 C20.1 C21.1 J10.0@-3568.5,2244.5 J10.1 J10.2 J10.3 J10.4 J10.5 J10.6 K1.4 R1.2 R2.2 U2.1 U4.1 U4.2 U4.3 U5.1 U7.1 | length 14433.8
  Top Layer w50: J10.6 -3470,922 -3238,690 C20.1@-3140,690 ; C1.1 -3020,-2290 K1.4 -2623.25,-2059 -1739,-2059 R1.2
  Bottom Layer w50: J10.0@-3568.5,2244.5 -3470,2146 J10.1 ; J10.6 J10.5 J10.4 J10.3 J10.2 J10.1 ; C20.1@-3140,690 -3040,690 -2940,690 -2840,690 -2740,690 -2610,560 -1920,560 -1820,560 -1720,560 -1620,560 C16.1@-1520,560 ; C19.1 -2400,1680 -2740,2020 -2840,2020 -2940,2020 -3040,2020 -3140,2020 -3305,2020 -3325,2000 J10.1 ; C10.1@-1920,2650 -1820,2650 -1720,2650 C10.1@-1620,2650 ; C10.1@-1520,2650 C10.1@-1620,2650 ; R1.2 -1490,-500 U4.1 ; U5.1 -1550,2580 C10.1@-1620,2650 ; U2.1 -420,-1180 C2.1 -420,-900 ; R2.2 -420,-900 ; C10.1@-1620,2650 -1620,2280 C9.1 C15.1 -1600,1250 U7.1 -1520,690 C16.1@-1520,560 ; U4.1 -1090,-900 -420,-900 ; U4.1 U4.2 U4.3 -1530,254 -1520,264 C16.1@-1520,560
ELECCUR: J8.3 U4.a | length 354.7
  Bottom Layer w10: U4.a -1599,-841 -1599,-1009 J8.3
IRID5V+: C25.1 J15.1 J16.1 R9.1 U11.3 | length 2150.4
  Top Layer w30: C25.1 2340,980 2380,1020 U11.3 2650,1090 R9.1 3620,1090 3680,1030 J16.1
  Bottom Layer w30: J16.1 J15.1
ISO5VSENSE+: J9.3 U5.5 | length 1530.9
  Top Layer w10: U5.5 450,2350 450,2509 619,2678 1404,2678 J9.3
ISO5VSENSE-: J9.9 R6.2 U5.8 | length 1350.6
  Top Layer w10: U5.8 960,3080 R6.2 1358,3040 1447,2951 1680,2951 J9.9
LOCO+: C7.1 C8.1 J7.3 U3.1 U3.2 U3.3 | length 1659.3
  Bottom Layer w50: J7.3 -3070,-1140 -2740,-1470 -2640,-1470 -2540,-1470 -2440,-1470 -2340,-1470 -2330,-1480 -1930,-1480 C7.1 ; C8.1@-2460,-1470 U3.1 U3.2 U3.3
LOCOCUR: J8.2 U3.a | length 1130.7
  Top Layer w10: U3.a -2710,-1160 J8.2
MVC3.3V+: C23.1 J13.1 J14.1 R12.1 U10.3 | length 2207.4
  Top Layer w30: C23.1 2400,2590 2460,2650 U10.3
  Top Layer w50: U10.3 2580,2690 2640,2750 R12.1 3450,2550 3620,2550 3680,2610 J14.1
  Bottom Layer w50: J14.1 J13.1
MVC5V+: C11.1 C12.1 J9.1 J9.2 J9.4 J9.5 J9.6 J23.1 R8.1 U5.6 U14.1 U14.3 U15.8 | length 9645.1
  Top Layer w20: U14.1 3060,-2270 3050,-2260 3050,-2160 ; U14.3 3060,-2170 3050,-2160 ; U15.8 3080,-1850 3050,-1880 3050,-2160
  Top Layer w30: U5.6 570,2530 C12.1 ; C12.1@880,2530 880,2540 940,2600 C11.1 1523,2600 J9.2 ; U14.1 v2(3256,-2270)
  Top Layer w50: R8.1 C12.1
  Bottom Layer w30: 1470,2350 1470,-418 1900,-848 1900,-1560 2173,-1833 2323,-1833 2656,-2166 2656,-2316 2734,-2394 3132,-2394 v2(3256,-2270) 3256,-2283 3645,-2283 3680,-2248 J23.1
  Bottom Layer w50: 1470,2350 J9.1 J9.2 1440,2797 1440,2911 J9.4 J9.5 J9.6
MVC12V+: C13.1 C17.1 C18.1 C22.1 C24.1 J12.0@1678.5,1189.5 J12.1 J12.2 J12.3 J12.4 J12.5 J12.6 R10.1 U6.2 U7.5 U7.6 U10.1 U11.1 | length 7993.9
  Top Layer w30: U7.5 600,710 R10.1 ; U10.1 2900,2650 2960,2590 C22.1
  Top Layer w50: U7.6 520,890 540,910 C18.1 937,910 1007,980 C17.1 1545,980 J12.6 ; J12.0@1678.5,1189.5 1860.5,1189.5 2120,930 2120,690 2450,360 C13.1 2710,320 U6.2 ; U11.1 2960,840 C24.1
  Bottom Layer w30: U7.5 U7.6 ; U11.1 U10.1
  Bottom Layer w50: J12.1 J12.2 J12.3 J12.4 J12.5 J12.6 1580,1091 J12.0@1678.5,1189.5 ; U11.1 2780,530 2990,320 U6.2
MVCGND: C11.2 C12.2 C13.2 C17.2 C18.2 C22.2 C23.2 C24.2 C25.2 D9.3 D10.3 D11.3 D12.3 J9.7 J9.8 J9.10 J9.11 J9.12 J12.0@1678.5,-284.5 J12.7 J12.8 J12.9 J12.10 J12.11 J12.12 J13.2 J14.2 J15.2 J16.2 J23.3 R7.2 R19.2 U5.7 U6.1 U7.7 U7.8 U10.2 U11.2 U14.4 U15.5 U15.7 | length 24313
  Top Layer w20: U7.7 390,1100 390,610 470,530 1007,530 D10.3 ; D12.3 3500,1550 3570,1480 J15.2
  Top Layer w30: U7.8 643,1430 663,1410 R7.2 1497,2107 ; U5.7 520,2810 540,2790 C12.2 995,2790 C11.2 ; D9.3 1093,2443 1161,2443 1497,2107 ; J12.9 1971,160 C13.2 2945,160 ; J9.7 1830,2407 1830,2175.72 1734.64,2080.36 1523.64,2080.36 1497,2107 ; C23.2 C22.2 2760,2535 2680,2615 U10.2 ; U6.1 3005,220 2945,160 ; U14.4 3114.41,-2120 U15.5 ; 3114.41,-2060 3190,-2060 3400,-2060 3480,-2140 J23.3 3480,-1900 ; U15.7 3480,-1900 ; D11.3 3283,3195 3580,3195 J13.2 ; R19.2 3627,-2388 3768,-2388 3768,-1900 ; 2945,160 3194,-89 3400,-89 3554,-243 3645,-243 3768,-366 3768,-1900 ; 3480,-1900 3768,-1900
  Top Layer w50: U7.7 580,1170 C18.2 995,1170 C17.2 ; C25.2 2680,870 ; U11.2 2680,870 ; J16.2 3380,980 3040,640 2800,640 2760,680 C24.2 2680,870
  Bottom Layer w30: U7.7 U7.8 440,1510 440,2800 U5.7
  Bottom Layer w50: J12.0@1680,-280 1777,-183 J12.7 J12.8 J12.9 J12.10 J12.11 J12.12 1841,989 1841,2307 1777,2351 J9.7 J9.8 1910,2790 1910,2918 J9.10 J9.11 J9.12 ; U6.1 2740,220 2680,280 U11.2 U10.2 2680,2710 2720,2750 3500,2750 J14.2 J13.2 ; J16.2 J15.2
NetB1_1: B1.1 J20.1 | length 1162.4
  Bottom Layer w10: B1.1 -2300,3550 J20.1
NetB1_2: B1.2 J20.2 | length 868.3
  Bottom Layer w10: B1.2 -2200,2840 J20.2
NetC5_1: C5.1 R3.2 R4.1 | length 585.1
  Top Layer w10: R4.1 -1982,-2930 -1966.39,-2945.61 -1825.61,-2945.61 -1815,-2935 -1795,-2935 R3.2 -1865,-3090 C5.1
NetC26_2: C26.2 R15.2 R16.1 U12.11 | length 710.1
  Top Layer w10: U12.11 1640,-910 1645,-905 C26.2 R15.2 ; v1(1810,-1040) 1820,-1050 R16.1
  Bottom Layer w10: U12.11 1660,-1040 v1(1810,-1040)
NetC30_1: C30.1 U16.16 Y1.4 | length 350
  Top Layer w10: U16.16 2721,-1130 2721,-1118.27 Y1.4 C30.1
NetC31_1: C31.1 U16.15 Y1.1 | length 352.4
  Top Layer w10: U16.15 2600,-1260 Y1.1 C31.1
NetC33_1: C33.1 C34.2 U17.16 | length 299.1
  Top Layer w10: C33.1 U17.16 2785,-640 2795,-650 C34.2
NetC33_2: C33.2 C36.1 U17.15 | length 624.9
  Top Layer w10: U17.15 2695,-590 C33.2 2610,-291 2660,-241 2739,-241 C36.1
NetC34_1: C34.1 U17.2 | length 214.1
  Top Layer w10: C34.1 2930,-600 2940,-590 U17.2
NetC35_1: C35.1 U17.1 | length 186.6
  Top Layer w10: U17.1 3060,-640 3100,-680 C35.1
NetC35_2: C35.2 U17.3 | length 163.3
  Top Layer w10: U17.3 3080,-540 3100,-560 C35.2
NetC36_2: C36.2 U17.6 | length 252.1
  Top Layer w10: C36.2 2935,-213 2934.29,-213.71 2934.29,-383.29 2941,-390 U17.6
NetC37_1: C37.1 U17.4 | length 140
  Top Layer w10: U17.4 2999,-490 2999,-470 C37.1
NetC37_2: C37.2 U17.5 | length 175.8
  Top Layer w10: U17.5 3016,-440 3026,-430 3026,-409 C37.2
NetC38_1: C38.1 J11.2 U8.8 | length 482.4
  Top Layer w10: J11.2 -3100,3493 -3080,3473 C38.1 -3080,3280 -3070,3270 U8.8
NetC38_2: C38.2 J11.1 U8.4 | length 676.7
  Top Layer w10: U8.4 -3325,3120 -3335.61,3130.61 -3335.61,3291.39 -3272,3355 -3270,3355 C38.2 v1(-3215,3483)
  Bottom Layer w10: v1(-3215,3483) -3200,3498 J11.1
NetD1_2: D1.2 K1.8 R1.1 | length 444.8
  Top Layer w10: -1720,-2565.28 -1720,-2510 D1.2
  Top Layer w30: K1.8 -1740,-2585.28 -1720,-2565.28 ; D1.2@-1720,-2510 R1.1
NetD3_2: D3.2 K2.8 R2.1 | length 743.4
  Top Layer w10: 778.74,-1030.26 780,-1029
  Top Layer w20: D3.2 778.74,-1030.26 ; 780,-1029 R2.1
  Bottom Layer w30: R2.1 780,-1304.72 K2.8
NetD5_2: D5.2 J4.1 R3.1 | length 1725.4
  Top Layer w10: D5.2 -1791,-3260 D5.2@-1774.5,-3276.5 ; R3.1 -1710,-3212 D5.2@-1774.5,-3276.5 ; J4.1 -530,-3634 -717,-3447 -1604,-3447 D5.2@-1774.5,-3276.5
NetD9_2: D9.2 R8.2 | length 110
  Top Layer w10: R8.2 D9.2
NetD10_2: D10.2 R10.2 | length 324.9
  Top Layer w10: R10.2 945,775 960,790 1100,790 1145,745 D10.2
NetD11_2: D11.2 R12.2 | length 212.1
  Top Layer w10: R12.2 3245,2890 D11.2 D11.2@3250,3090
NetD12_2: D12.2 R9.2 | length 263.6
  Top Layer w10: D12.2 3235,1270 R9.2
NetD13_2: D13.2 R14.2 | length 179.1
  Top Layer w10: R14.2 3355,155 3371,155 3376,160 D13.2
NetD14_2: D14.2 R11.2 | length 337.8
  Top Layer w10: D14.2 -1125,-3820 -1112,-3833 -1016,-3833 -1016,-3631 R11.2
NetD15_1: D15.1 K3.1 U13.1 U13.2 | length 841.4
  Top Layer w10: D15.1 D15.1@1130,-2228
  Top Layer w20: D15.1@1130,-2228 1178,-2228 K3.1 ; v1(1194,-1911) 1244,-1911 1295,-1860 U13.2 U13.1
  Bottom Layer w20: v1(1194,-1911) 1194,-2254 K3.1
NetD17_2: D17.2 R22.1 | length 135
  Top Layer w20: R22.1 D17.2
NetD19_1: D19.1 J17.4 U9.00 U9.6 | length 2864.9
  Top Layer w18: U9.6 1900,-2720 2540,-2720 ; J17.4 3440,-2940 U9.00 ; D19.1@2700,-2741.26 D19.1
  Top Layer w30: 2540,-2720 2560,-2740 D19.1 ; J17.4 D19.1@2700,-2741.26
NetF1_1: F1.1 K3.4 R22.2 | length 1399.6
  Top Layer w10: F1.1@2200,-2365 F1.1
  Top Layer w18: K3.4 1710,-2160 1710,-1835 R22.2
  Top Layer w50: K3.4 1560,-2390 1600,-2430 2080,-2430 F1.1
NetJ3_1: J3.1 U17.14 | length 1250.4
  Top Layer w10: U17.14 2788,-540 2798,-550 2798,-581 2863,-646 2863,-829 2884,-850 3340,-850 3420,-770 3600,-770 J3.1
NetJ3_2: J3.2 U17.13 | length 1023.4
  Top Layer w10: U17.13 2818,-490 2852,-524 v1(2852,-558)
  Bottom Layer w10: v1(2852,-558) 3286,-558 3527,-799 3570,-799 3580,-809 J3.2
NetJ5_1: 
NetJ5_2: 
NetJ11_3: J11.3 U8.1 | length 869
  Top Layer w10: U8.1 -3200,3270 -3169.59,3300.41 -3169.59,3540.59 -3251.34,3622.34 -3251.34,3722.52 -3213.86,3760 -3080,3760 J11.3
NetJ11_4: J11.4 U8.2 | length 666
  Top Layer w10: U8.2 -3180,3220 -3140,3260 v1(-3140,3285)
  Bottom Layer w10: v1(-3140,3285) -2900,3525 J11.4
NetJ11_5: J11.5 U8.3 | length 1050
  Top Layer w10: U8.3 -3180,3170 -3099.75,3089.75 -2874.25,3089.75 -2800,3164 J11.5
NetJ17_6: J17.6 U9.5 | length 1331.7
  Bottom Layer w10: U9.5 2281,-2840 2469,-3028 2469,-3649 J17.6
NetJ17_7: J17.7 R13.1 U9.4 | length 1096
  Top Layer w10: U9.4 2120,-2940 R13.1 v1(2400,-3220)
  Bottom Layer w10: J17.7 v1(2400,-3220)
NetJ17_8: J17.8 U9.0 U9.3 | length 3848.9
  Top Layer w10: U9.0 -870,-3040 U9.3
  Bottom Layer w10: U9.3 2125,-3040 2300,-3215 J17.8
NetJ17_9: J17.9 R13.2 U9.2 | length 855.4
  Top Layer w10: U9.2 2175,-3140 R13.2 v1(2180,-3230)
  Bottom Layer w10: v1(2180,-3230) 2180,-3660 J17.9
NetJ17_10: J17.10 U9.1 | length 531.1
  Bottom Layer w10: U9.1 2068,-3428 2068,-3648 J17.10
NetJ21_1: J21.1 U17.7 | length 1623.2
  Top Layer w10: U17.7 3020,-340 3040,-320 3040,-305 3055,-290 v1(3187,-290)
  Bottom Layer w10: v1(3187,-290) 3506,-609 3700,-609 3751,-660 3751,-1229 J21.1
NetJ21_2: J21.2 U17.8 | length 1607.6
  Top Layer w10: U17.8 2980,-270 v1(3010,-240)
  Bottom Layer w10: v1(3010,-240) 2780,-470 2780,-600 2930,-750 3030,-750 J21.2
NetJ21_3: 
NetR6_1: R6.1 U5.9 | length 670.5
  Top Layer w10: U5.9 786,3546 806,3546 R6.1
NetR7_1: R7.1 U7.9 | length 596
  Bottom Layer w10: U7.9 800,1910 R7.1
NetR17_1: R17.1 U14.6 U16.6 | length 1398.6
  Top Layer w10: U16.6 2420,-1580 2701,-1580 2948.99,-1827.99 2948.99,-2141.01 2920,-2170 U14.6 2790,-2170 R17.1
NetR20_1: R20.1 U13.5 | length 219
  Top Layer w10: U13.5 1370,-1640 1395,-1615 1395,-1565 R20.1
NetR20_2: R20.2 U16.17 | length 1294
  Top Layer w10: R20.2 1795,-1385 2025.51,-1154.49 2208.49,-1154.49 2229,-1175 2425,-1175 U16.17
NetR21_1: R21.1 U13.3 | length 192.1
  Top Layer w10: R21.1 1290,-1604 1295,-1609 U13.3
NetR25_2: R25.2 R26.2 U1.1 | length 1140.2
  Top Layer w10: U1.1 -1210,-1440 -1380,-1610 -1380,-1830 -1255,-1955 R25.2 -910,-1815 R26.2
NetU15_2: U15.2 U16.18 | length 1305.3
  Top Layer w10: v1(2650,-1900) U15.2
  Bottom Layer w10: U16.18 2495,-1005 2495,-1405 2500,-1410 2500,-1703 2500,-1750 v1(2650,-1900)
PARO9V+: C14.1 J1.1 R14.1 U6.4 | length 1526
  Top Layer w30: U6.4 3120,590 C14.1 3630,590 3657,563 3657,480 3657,461 3659,459 3680,438 ; R14.1 3380,20 3680,320 3680,438 ; J1.1 3680,438
PARO9VGND: C14.2 D13.3 J1.2 U6.3 | length 779
  Top Layer w30: U6.3 3138,420 3168,390 C14.2 3393,390 3468,315 ; D13.3 3468,315 ; J1.2 3580,427 3468,315
PICRX: U16.8 U17.9 | length 1585.4
  Top Layer w10: v1(2670,-290) U17.9
  Bottom Layer w10: U16.8 2436,-1464 2436,-524 v1(2670,-290)
PICTX: U16.11 U17.10 | length 2154
  Top Layer w10: v1(2540,-628) 2540,-278 2683,-135 2845,-135 2845,-332 2837,-340 U17.10
  Bottom Layer w10: v1(2540,-628) 2615,-703 2615,-1260 2600,-1275 2540,-1275 2515,-1300 2515,-1385 2525,-1395 2525,-1560 2540,-1575 2560,-1575 2570,-1585 U16.11
PTT-TTL-SER-RX: J19.4 U17.12 | length 1275.8
  Top Layer w10: U17.12 2825,-440 2885,-500 2885,-806 3224,-806 3380,-650 J19.4
PTT-TTL-SER-TX: J19.3 U17.11 | length 1078.1
  Top Layer w10: U17.11 2820,-390 2870,-340 2870,-160 2895,-135 3261,-135 3480,-354 J19.3
Q1G: D5.1 D6.2 Q1.1 R4.2 R5.2 | length 800.4
  Top Layer w10: Q1.1 -2350,-3090 R5.2 -2275,-3140 D6.2 -2125,-3140 -2018,-3140 -1978,-3180 -1978,-3260 D5.1 ; -2055,-3140 R4.2@-2055,-3065
RAWBUS+: D7.2 D8.2 J7.1 J7.2 U3.4 U3.5 U3.6 U4.4 U4.5 U4.6 | length 1845.9
  Bottom Layer w50: J7.1 J7.2 -3013,-860 U3.6 U3.5 U3.4 -2260,-760 D7.2 -2030,-530 U4.6 U4.5 ; D8.2 U4.5 ; U4.4 U4.5
RAWBUS-: C1.2 C2.2 C4.2 C5.2 C6.2 C7.2 C8.2 C9.2 C10.2 C15.2 C16.2 C19.2 C20.2 C21.2 C32.2 D1.1 D3.1 D4.1 D6.1 D7.1 D8.1 J7.0 J7.4 J7.5 J7.6 J10.0@-3568.5,770.5 J10.7 J10.8 J10.9 J10.10 J10.11 J10.12 J19.2 J22.2 J22.4 K1.1 K2.1 Q1.3 R5.1 U2.2 U5.2 U7.2 U9.7 | length 27933.9
  Top Layer w20: C6.2 -3267,-1654.87 J7.0@-3267,-1358.5
  Top Layer w50: Q1.3 -2401,-2741 -2201,-2741 -1990,-2530 ; R5.1 -2350,-2890 D6.1 ; -1920,-2850 C5.2 -1990,-2780 -1990,-2410 K1.1 -1730,-2290 -1720,-2300 D1.1 ; C7.2 -1406,-1316 -499,-1316 -477.5,-1337.5 ; C16.2@-1520,960 -1350,1130 U7.2 ; C4.2 C2.2 -320,-1180 -477.5,-1337.5 ; K2.1 540,-1278 ; D3.1 560,-1160 540,-1180 540,-1278 ; U9.7 D4.1@2170,-2640 ; D4.1 D4.1@2170,-2640 ; C32.2 v2(3565,-491) ; v2(3824,-2497) 2213,-2497 2170,-2540 D4.1@2170,-2640 ; -477.5,-1337.5 -377.37,-1437.63 -162.63,-1437.63 -140,-1415 U2.2 -140,-1318 -100,-1278 540,-1278
  Bottom Layer w30: 3805.62,-318.72 3840,-353.11 3840,-2480 3840,-2481 v2(3824,-2497)
  Bottom Layer w50: J10.7 J10.8 J10.9 J10.10 J10.11 J10.12 -3568.5,916.5 J10.0@-3568.5,770.5 ; J22.4 -3251,-2922 -3251,-2723 -3251,-2540 -3251,-1374.5 -3267,-1358.5 J7.6 J7.5 J7.4 J7.0@-3267,-475.5 ; J22.2 -3298,-2717 -3251,-2670 ; J7.0@-3270,-1370 J7.0@-3240,-1370 ; J7.0@-3260,-1370 -2760,-1870 -2740,-1870 -2640,-1870 -2540,-1870 -2440,-1870 -2340,-1870 -2350,-1880 -1970,-1880 C7.2 -1900,-1876 -1900,-2290 K1.1 ; -3251,-2260 -3211,-2300 C1.2 ; C21.2@-3140,1620 -3040,1620 -2940,1620 C21.2@-2840,1620 ; D7.1 -2790,-591 -2905.5,-475.5 ; D8.1 -2905.5,-475.5 ; C21.2@-2740,1620 C21.2@-2840,1620 ; C16.2@-1520,960 -1620,960 -1720,960 -1820,960 -1920,960 -1920,1150 -1900,1170 C15.2 ; U5.2 -1405,2905 -1405,2935 -1520,3050 -1620,3050 -1720,3050 -1820,3050 -1920,3050 -1998,2972 -1998,2378 C9.2 C15.2 ; K2.1 1000,-1820 1000,-2228 1412,-2640 U9.7 ; v2(3565,-491) 3580,-476 J19.2 3580,-348 3609.28,-318.72 3805.62,-318.72 ; J10.0@-3568.5,770.5 -3459.5,770.5 -3140,1090 -3040,1090 -2940,1090 C20.2@-2840,1090 ; J10.0@-3568.5,770.5 -3568.5,438.5 -3267,137 J7.0@-3267,-475.5 ; J7.0@-3267,-475.5 -2905.5,-475.5 ; C20.2@-2840,1090 -2740,1090 -2630,1200 C19.2 -2260,1340 C15.2 ; C20.2@-2840,1090 C21.2@-2840,1620
SHIELD: C6.1 J7.7 J7.8 J7.9 | length 1111.9
  Top Layer w10: C6.1 -3614.09,-1264.09 J7.9
  Bottom Layer w10: J7.9 J7.8 J7.7
SW10VDC: D4.2 J17.5 K2.3 | length 4042.6
  Top Layer w30: D4.2 2170,-2810 2466,-3106 2466,-3309 2600,-3443 J17.5
  Bottom Layer w50: K2.3 680,-2287.4 680,-2550 1930,-3800 2540,-3800 2600,-3740 J17.5
V+PTT: C32.1 D19.2 J19.1 | length 3372.8
  Top Layer w10: J19.1 3680,-560 C32.1
  Top Layer w30: D19.2 3457,-2740 v1(3461,-2736)
  Bottom Layer w10: J19.1@3680,-420 J19.1
  Bottom Layer w30: v1(3461,-2736) 3464,-2736 3790,-2410 3790,-440 3750,-400 J19.1
V+USBL: C3.1 D18.1 J18.3 R25.1 U1.2 | length 2862
  Top Layer w30: C3.1 -1300,-1659 -1279.59,-1638.59 -1135.41,-1638.59 -1134,-1640 D18.1 ; R25.1 -1048.74,-1818.74 D18.1 ; U1.2 -1020,-1550 -1048.74,-1578.74 D18.1
  Bottom Layer w30: J18.3 -1996,-3499 -1717,-3220 -1717,-2172 -1300,-1755 C3.1
WDC: J23.2 R19.1 U14.2 | length 707
  Top Layer w10: U14.2 3290,-2220 3390,-2320 3390,-2370 3410,-2390 R19.1 3580,-2300 J23.2
WDSTATUS: J23.4 U15.6 | length 503.9
  Top Layer w10: U15.6 3360,-1950 v1(3380,-1970)
  Bottom Layer w10: J23.4 v1(3380,-1970)
pads on no net: D9.1 D10.1 D11.1 D12.1 D13.1 D14.1 D17.1 F2.1 F2.2 J9.0 J18.0 J22.0 K1.5 K1.6 K1.7 K2.5 K2.6 K2.7 K3.2 K3.3 K3.5 K3.6 K3.7 K3.10 K3.11 K3.12 K3.14 K3.15 U2.0 U5.3 U5.4 U7.3 U7.4 U8.5 U8.6 U8.7 U10.0 U11.0 U12.1 U12.4 U12.5 U12.6 U12.7 U12.8 U12.10 U12.12 U12.13 U12.14 U16.2 U16.3 U16.7 U16.9 U16.10 U16.12 U16.13 Y1.2 Y1.3

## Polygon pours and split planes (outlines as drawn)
no net on Internal Plane 1 (split plane): -3869.99,-3869.99 -3869.99,3869.99 3869.99,3869.99 3869.99,-3869.99
no net on Internal Plane 2 (split plane): -3869.99,-3869.99 -3869.99,3869.99 3869.99,3869.99 3869.99,-3869.99

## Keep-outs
Keep-Out Layer:
  circle w10: c3700,3700 r200
  circle w10: c0,3700 r200
  circle w10: c-3700,3700 r200
  circle w10: c-3700,0 r200
  circle w10: c0,0 r200
  circle w10: c3700,0 r200
  circle w10: c3700,-3700 r200
  circle w10: c0,-3700 r200
  circle w10: c-3700,-3700 r200
  circle w10: c-5375,-5375 r125
  lines w10: -5480,-5480 5480,-5480 5480,5480 -5480,5480 -5480,-5480 ; -3880,-3880 3880,-3880 3880,3880 -3880,3880 -3880,-3880
  text ".GKO" at 12740,-6040 h90

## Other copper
Top Layer:
  text ".GTL" at 12740,-6040 h90
Bottom Layer:
  text "94V-0" at 627.07,-3841.21 h50
  text ".GBL" at 12740,-6040 h90

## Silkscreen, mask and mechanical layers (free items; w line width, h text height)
Top Overlay:
  lines w10: -1267,-114 -1235,-116 -1204,-134 -1103,-225 -1090,-221 -1083,-222 -969,-309 ; -1212,-132 -1109,-229 ; -1104,-232 -1089,-228 -974,-316 ; -987,-332 -941,-305 -882,-251 -879,-244 -879,-234 -881,-231 -887,-230 -894,-230 ; -956,-330 -909,-367 ; -952,-323 -904,-361 -752,-223 -743,-219 -729,-224 -650,-138 -647,-143 -618,-117 -598,-113 ; -880,-245 -880,-237 -882,-233 -887,-231 -894,-230 ; -746,-227 -731,-232 ; -724,-228 -659,-155 ; -656,-158 -650,-149 ; -894,-230 -901,-233 -944,-253 -961,-264 -984,-268 -988,-263 -987,-251 -949,-219 -881,-172 -870,-156 -874,-145 -880,-143 -904,-149 -940,-169 -988,-197 -1018,-207 -1022,-203 -1011,-188 -993,-173 -971,-143 -953,-133 -938,-126 -925,-118 -918,-107 -883,-107 -860,-102 -844,-96 -828,-91 -811,-81 -816,-85 -845,-90 -862,-90 -819,-51 -868,-59 -907,-77 -950,-105 -989,-139 -1017,-166 -1039,-191 -1043,-199 -1044,-205 -1041,-212 -1036,-216 -1028,-221 -1018,-220 -890,-150 -880,-147 -873,-147 -869,-149 -867,-153 -865,-158 -868,-165 -876,-174 -971,-239 -982,-247 -986,-255 -987,-261 -983,-268 -976,-270 -968,-268 -894,-230 ; -903,-372 -744,-227 -903,-372
  text "M  B  A  R  I" at -1270,-60 h55
  text "Copyright 2003 MBARI" at -1240,-500 h45
  text "1002131-MVCPowerR2" at -1235,-583.32 h45
  text "2003-DEC-29" at -1235,-663.32 h45
  text "Made in U.S.A." at -1235,-733.32 h45
  text "ADUM" at 2980,-1850 h45 r270
  text "ADUM" at 3020,-2270 h45 r90
  text "Spare" at 2420,-2450 h45
  text ".GTO" at 12740,-6040 h90
Bottom Overlay:
  text ".GBO" at 12750,-6040 h90
Top Solder:
  text ".GTS" at 12740,-6040 h90
Bottom Solder:
  text ".GBS" at 12740,-6040 h90
Drill Guide:
  text ".GG1" at 9950,-6040 h90
Mechanical 4:
  circle w10: c-0.27,0 r4550.27
  circle w10: c0,0 r5500
  lines w10: -5500,-5500 5500,-5500 5500,5500 -5500,5500 -5500,-5500
Mechanical 16:
  lines w5: -6300,-3700 -6100,-3700 ; -6300,-1300 -6100,-1300 ; -6300,1100 -6100,1100 ; -6300,3500 -6100,3500 ; -6300,5900 -6100,5900 ; -3900,-6300 -3900,-6100 ; -3900,8100 -3900,8300 ; -1500,-6300 -1500,-6100 ; -1500,8100 -1500,8300 ; 900,-6300 900,-6100 ; 900,8100 900,8300 ; 3300,-6300 3300,-6100 ; 3300,8100 3300,8300 ; 5600,-6100 13100,-6100 ; 5700,-6300 5700,-6100 ; 5700,8100 5700,8300 ; 7200,-5500 13100,-5500 ; 8100,-6300 8100,-6100 ; 8100,8100 8100,8300 ; 8600,-5800 13100,-5800 ; 8600,-5200 10100,-5200 ; 10100,-6100 10100,-5500 10100,-4900 ; 10500,-6300 10500,-6100 ; 10500,8100 10500,8300 ; 12200,-6100 12200,-5500 ; 13100,-4900 10100,-4900 ; 13100,-3700 13300,-3700 ; 13100,-1300 13300,-1300 ; 13100,1100 13300,1100 ; 13100,3500 13300,3500 ; 13100,5900 13300,5900 ; 8600,-4900 7200,-4900 7200,-6100 8600,-6100 8600,-4900 ; 8600,-4900 10100,-4900 ; 13100,-6100 -6100,-6100 -6100,8100 13100,8100 13100,-6100 ; -6300,-6300 -6300,8300 13300,8300 13300,-6300 -6300,-6300
  lines w10: 7533,-5054 7565,-5056 7596,-5074 7697,-5165 7710,-5161 7717,-5162 7831,-5249 ; 7588,-5072 7691,-5169 ; 7696,-5172 7711,-5168 7826,-5256 ; 7813,-5272 7859,-5245 7918,-5191 7921,-5184 7921,-5174 7919,-5171 7913,-5170 7906,-5170 ; 7844,-5270 7891,-5307 ; 7848,-5263 7896,-5301 8048,-5163 8057,-5159 8071,-5164 8150,-5078 8153,-5083 8182,-5057 8202,-5053 ; 7920,-5185 7920,-5177 7918,-5173 7913,-5171 7906,-5170 ; 8054,-5167 8069,-5172 ; 8076,-5168 8141,-5095 ; 8144,-5098 8150,-5089 ; 7906,-5170 7899,-5173 7856,-5193 7839,-5204 7816,-5208 7812,-5203 7813,-5191 7851,-5159 7919,-5112 7930,-5096 7926,-5085 7920,-5083 7896,-5089 7860,-5109 7812,-5137 7782,-5147 7778,-5143 7789,-5128 7807,-5113 7829,-5083 7847,-5073 7862,-5066 7875,-5058 7882,-5047 7917,-5047 7940,-5042 7956,-5036 7972,-5031 7989,-5021 7984,-5025 7955,-5030 7938,-5030 7981,-4991 7932,-4999 7893,-5017 7850,-5045 7811,-5079 7783,-5106 7761,-5131 7757,-5139 7756,-5145 7759,-5152 7764,-5156 7772,-5161 7782,-5160 7910,-5090 7920,-5087 7927,-5087 7931,-5089 7933,-5093 7935,-5098 7932,-5105 7924,-5114 7829,-5179 7818,-5187 7814,-5195 7813,-5201 7817,-5208 7824,-5210 7832,-5208 7906,-5170 ; 7897,-5312 8056,-5167 7897,-5312
  text "7" at 9370,8170 h70
  text "8" at 11740,8170 h70
  text "1" at -4980,8160 h70
  text "2" at -2700,8160 h70
  text "3" at -340,8160 h70
  text "4" at 2010,8160 h70
  text "5" at 4470,8160 h70
  text "6" at 6840,8160 h70
  text "A" at -6230,7040 h70
  text "A" at 13170,7040 h70
  text "B" at -6240,4630 h70
  text "B" at 13160,4630 h70
  text "C" at -6220,2360 h70
  text "C" at 13180,2360 h70
  text "D" at -6240,-90 h70
  text "D" at 13160,-90 h70
  text "E" at -6220,-2600 h70
  text "E" at 13180,-2600 h70
  text "M  B  A  R  I" at 7530,-5000 h55
  text "ENGINEER:" at 8650,-5000 h45
  text "TITLE:" at 10150,-5000 h45
  text "Mark Sibenac" at 9160,-5030 h70
  text "F" at -6240,-5050 h70
  text "F" at 13160,-5050 h70
  text "Main Power Distribution" at 10500,-5120 h90
  text "1 831 775 2028" at 9150,-5170 h60
  text "PCB DESIGNER:" at 8650,-5295 h45
  text "Mark Sibenac" at 9160,-5330 h70
  text "MVC - Mapping AUV" at 10520,-5340 h90
  text "Copyright      2003" at 7380,-5350 h60
  text "Monterey Bay Aquarium Research Institute" at 7250,-5460 h45
  text "1 831 775 2028" at 9150,-5470 h60
  text "DATE:" at 8650,-5600 h45
  text "PART NO.:" at 10150,-5600 h45
  text "REV:" at 12250,-5600 h45
  text ".PRINT_DATE" at 8700,-5720 h70
  text "2" at 12530,-5720 h90
  text "MVCPOWR2" at 10510,-5730 h60
  text "M.B.A.R.I." at 7280,-5740 h100
  text "7700 Sandholdt Rd." at 7270,-5840 h60
  text "FILE NAME:" at 8650,-5900 h45
  text "DWG NO:" at 10150,-5900 h45
  text "GERBER:" at 12250,-5900 h45
  text "Moss Landing, CA 95039" at 7270,-5950 h60
  text "1002131-PCB" at 10510,-5990 h60
  text ".PCB_FILE_NAME_NO_PATH" at 8700,-6020 h70
  text ".GM16" at 12360,-6030 h70
  text "Fax: 1 831 775 1646" at 7270,-6050 h60
  text "7" at 9370,-6230 h70
  text "8" at 11740,-6230 h70
  text "1" at -4980,-6240 h70
  text "2" at -2700,-6240 h70
  text "3" at -340,-6240 h70
  text "4" at 2010,-6240 h70
  text "5" at 4470,-6240 h70
  text "6" at 6840,-6240 h70
Drill Drawing:
  text ".LEGEND" at 4445,-4630 h60
  text "Drill Drawing." at 4425,-4720 h60
  text ".GD1" at 9945,-6040 h90

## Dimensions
-5500,-5500 to 5500,-5500 on Mechanical 4
-5500,5500 to -5500,-5500 on Mechanical 4
-5375,-5375 to -5500,-5500 on Mechanical 4
-5375,-5375 to -5500,-5500 on Mechanical 4
-3890,-3890 to 3890,-3890 on Mechanical 4
3890,-3890 to 3890,3890 on Mechanical 4
-3890,-4040 to -3700,-3700 on Mechanical 4
3990,-3890 to 3700,-3700 on Mechanical 4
